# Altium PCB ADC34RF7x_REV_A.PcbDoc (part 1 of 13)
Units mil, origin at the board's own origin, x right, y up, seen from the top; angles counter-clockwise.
Board outline 6250 x 2716.54 mil, 18 copper layers (Top Layer, L2 GND, L3 PWR, L4 GND, L5 PWR/SIG, L6 GND, L7 SIGNAL, L8 GND, L9 GND, L10 SIGNAL, L11 GND, L12 SIGNAL, L13 GND, L14 PWR, L15 GND, L16 PWR/SIG, L16 GND, Bottom Layer), stack 95.314 mil thick; 668 components, 786 nets, 3150 pads, 2020 vias.
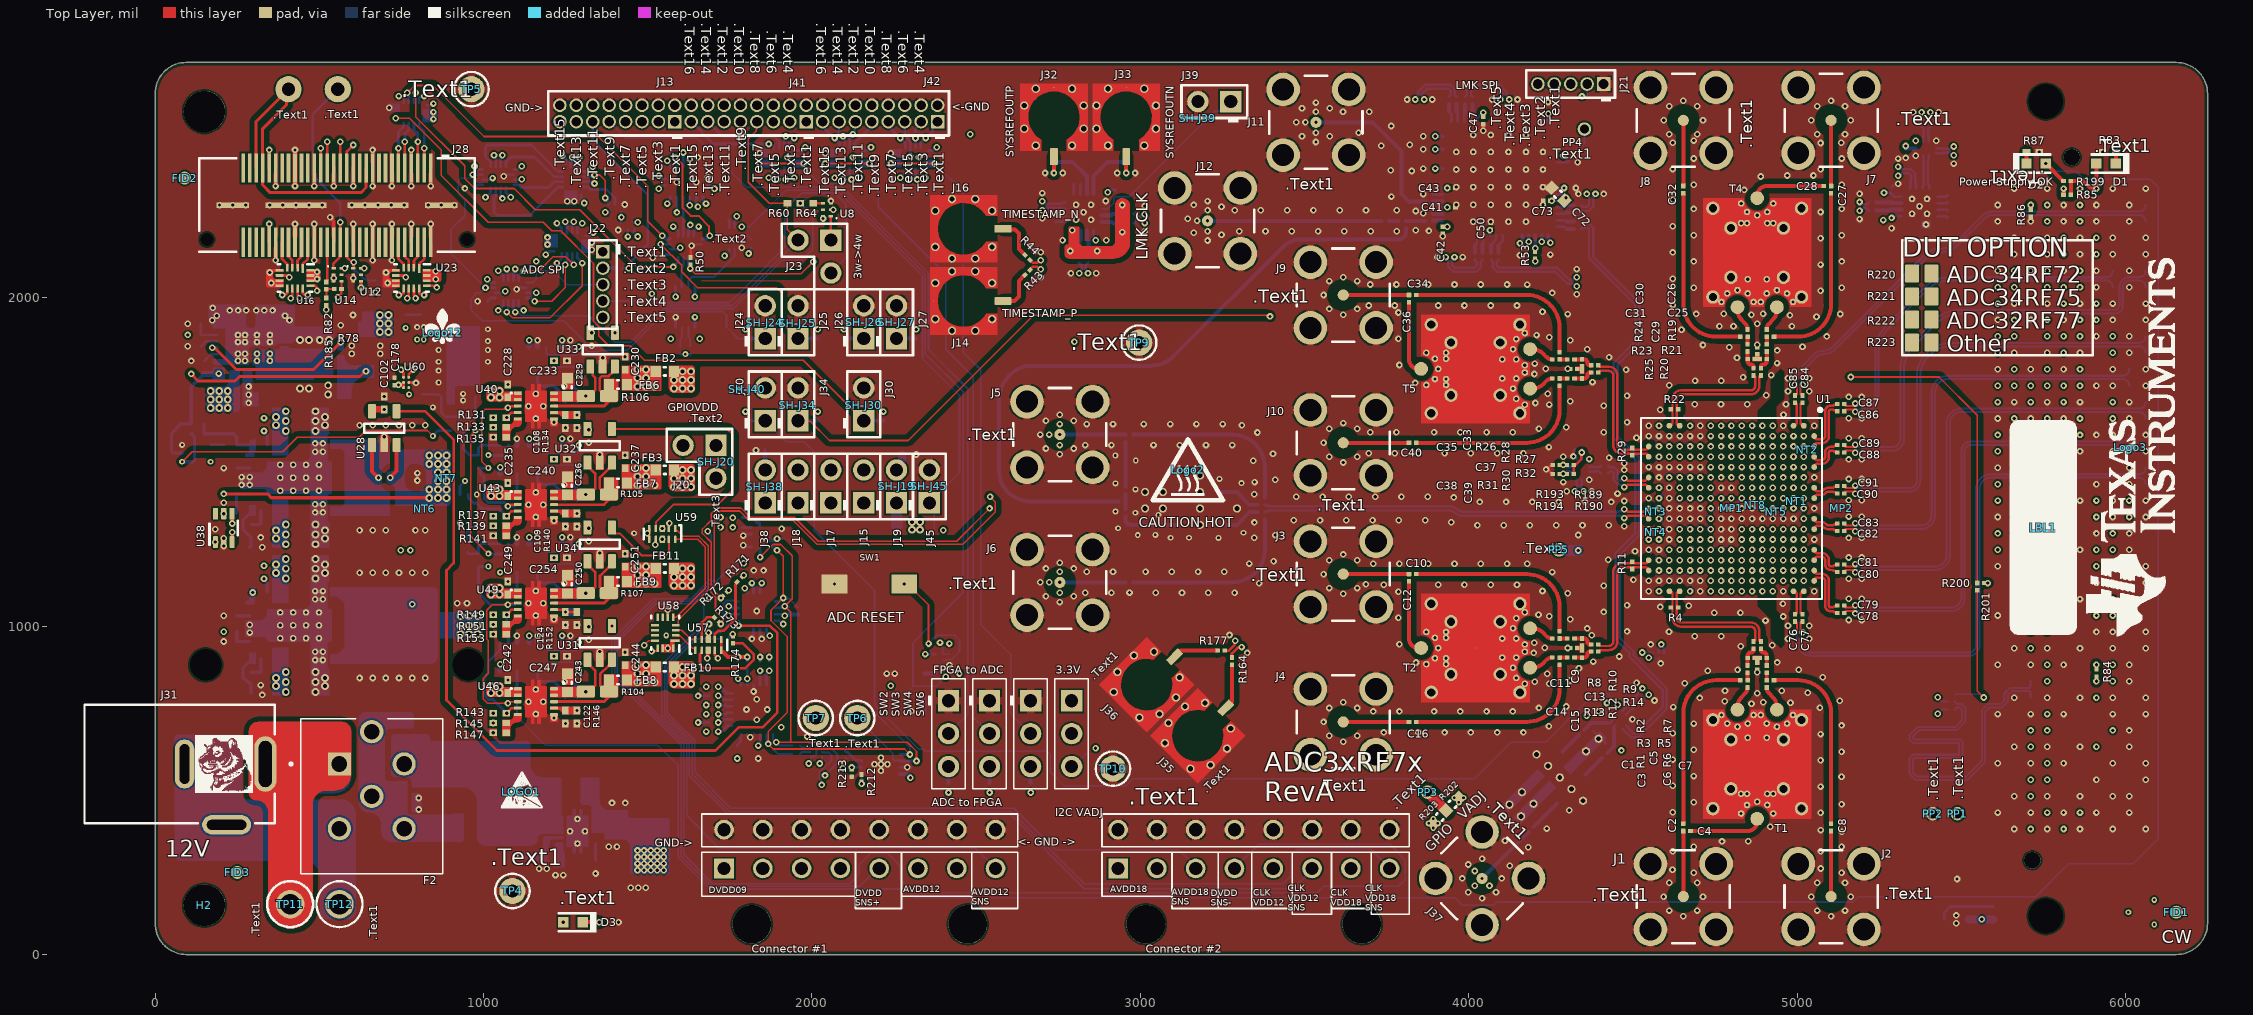
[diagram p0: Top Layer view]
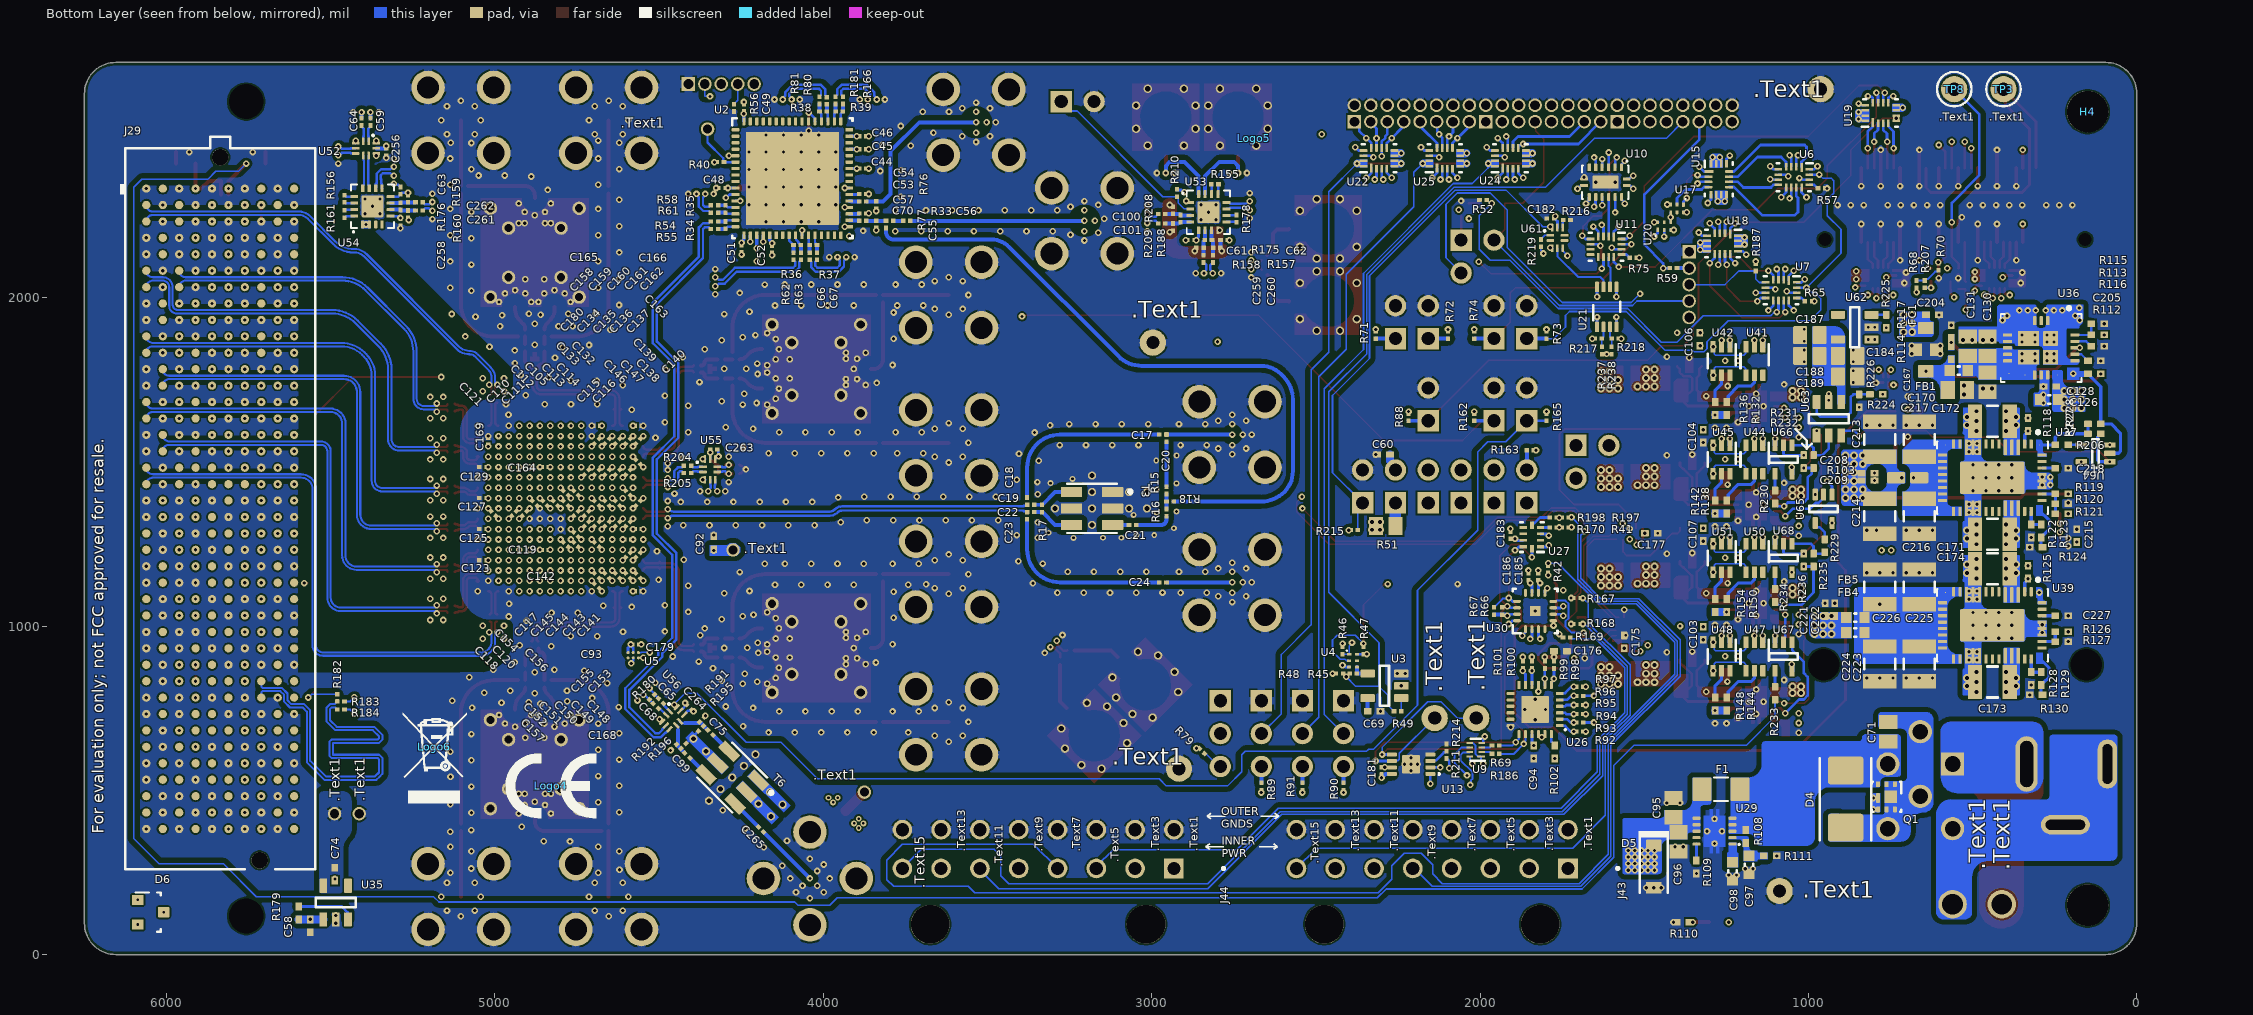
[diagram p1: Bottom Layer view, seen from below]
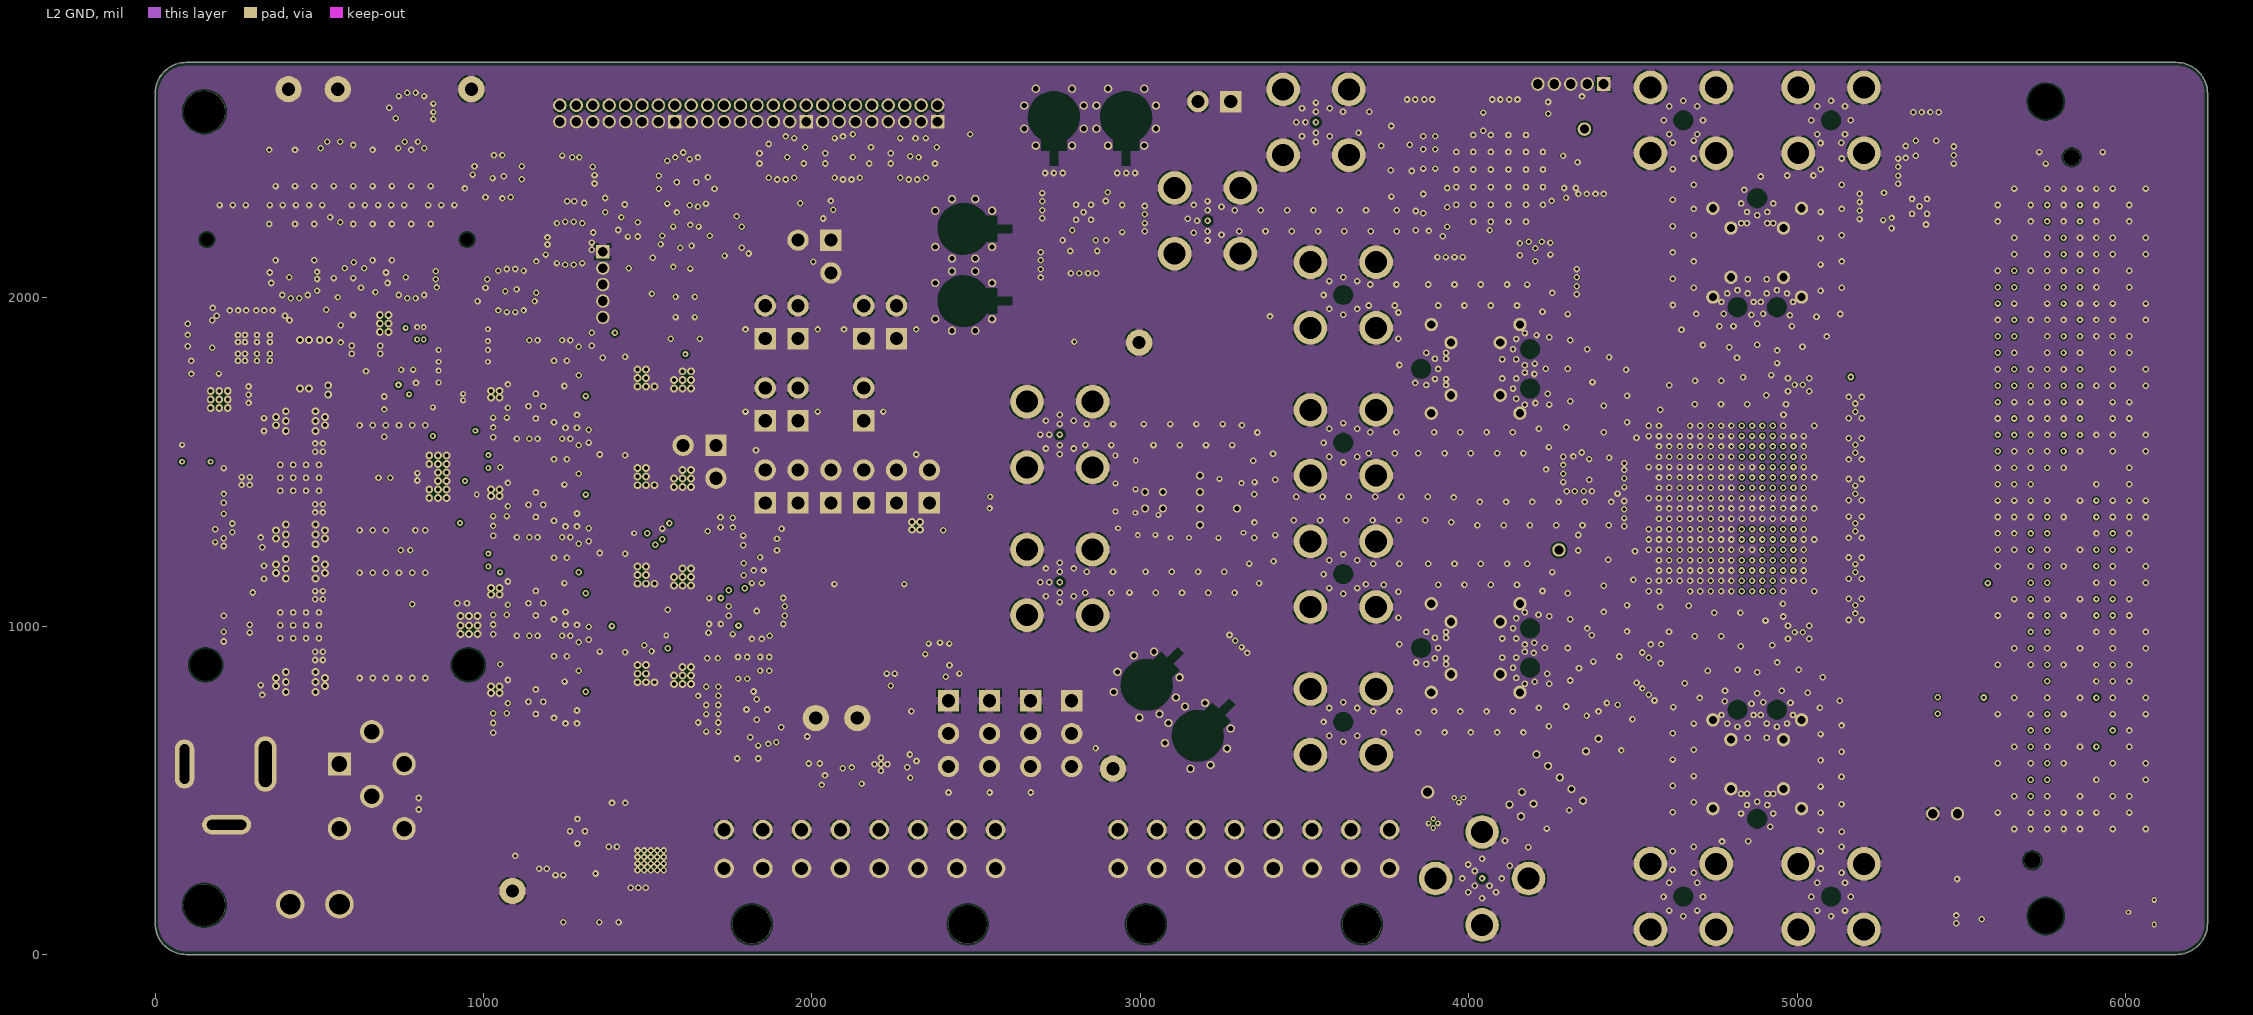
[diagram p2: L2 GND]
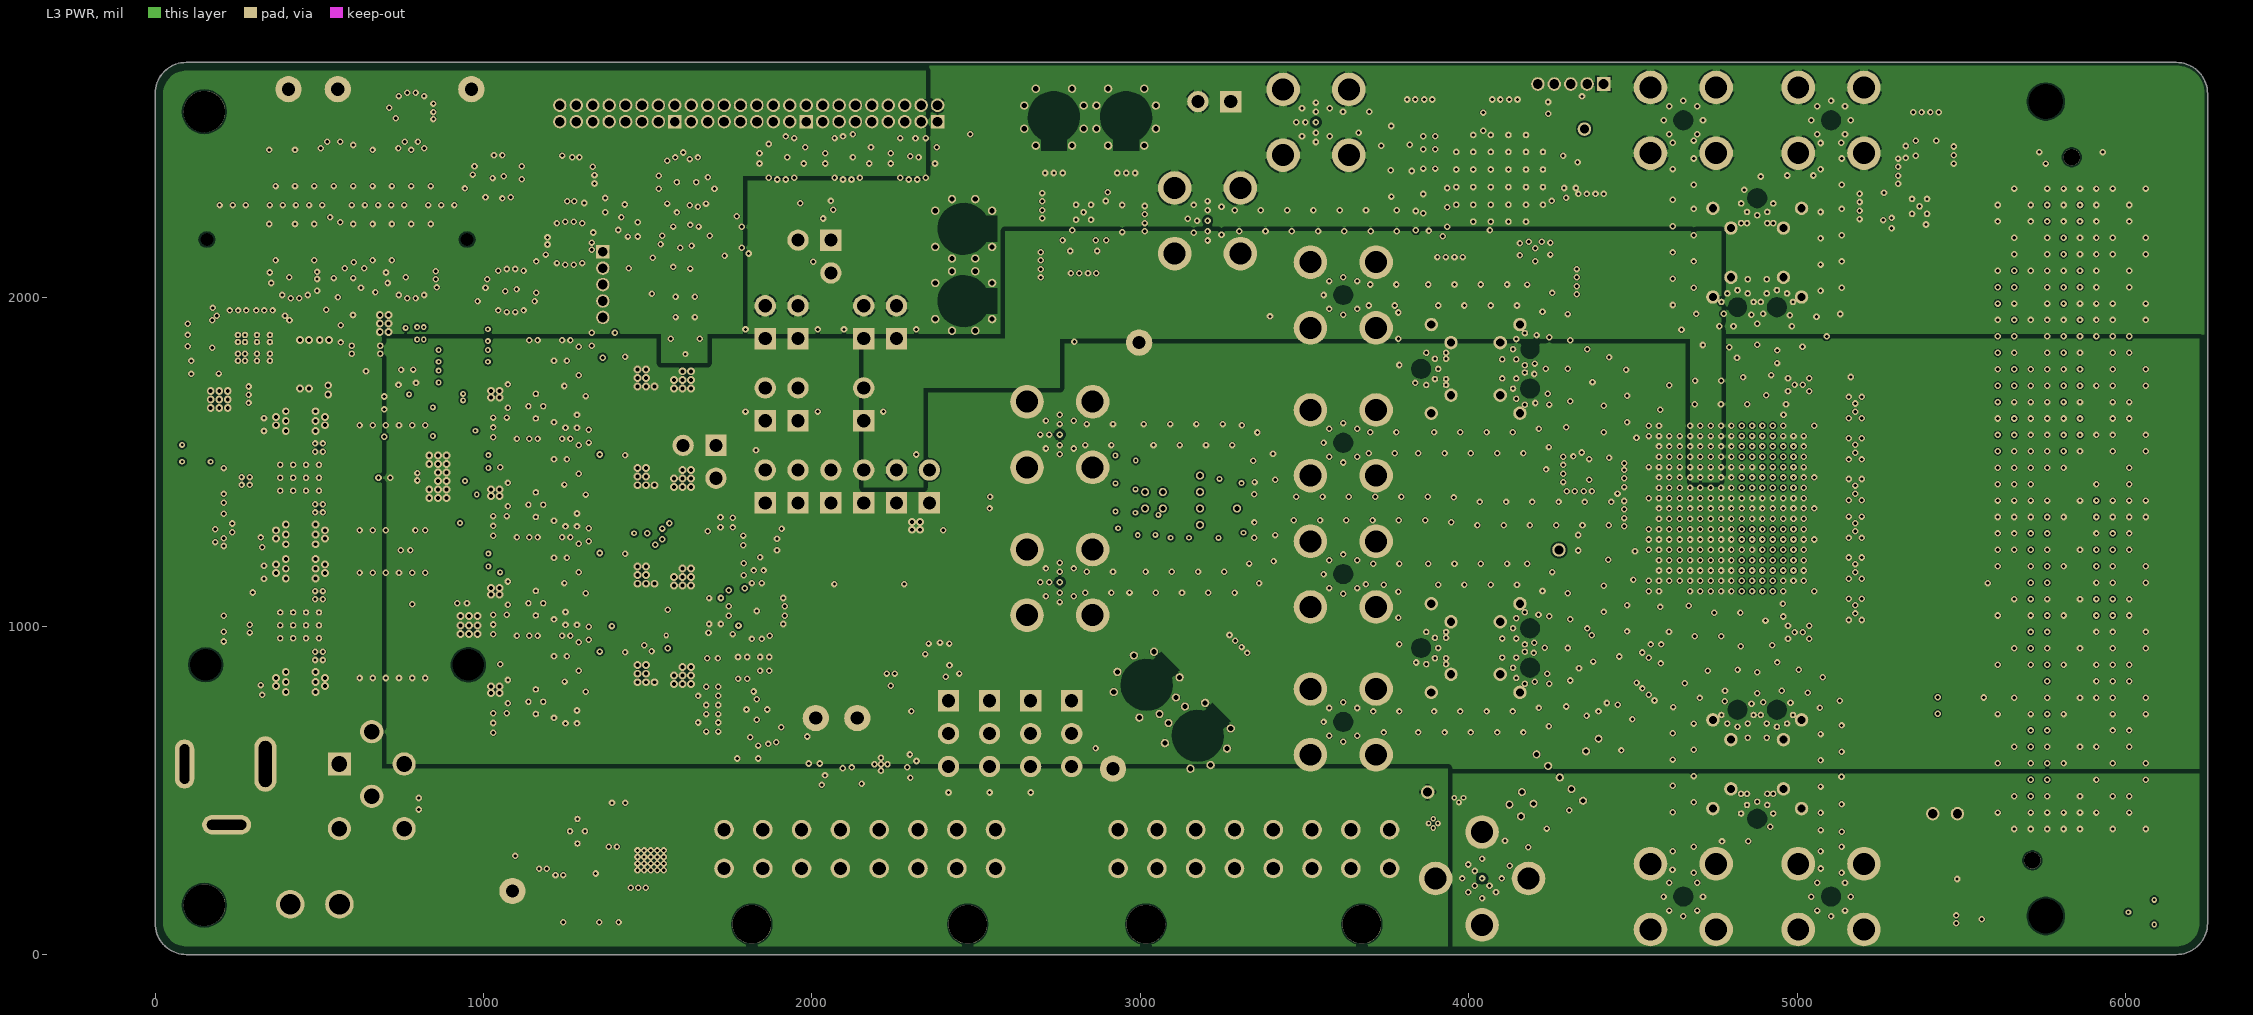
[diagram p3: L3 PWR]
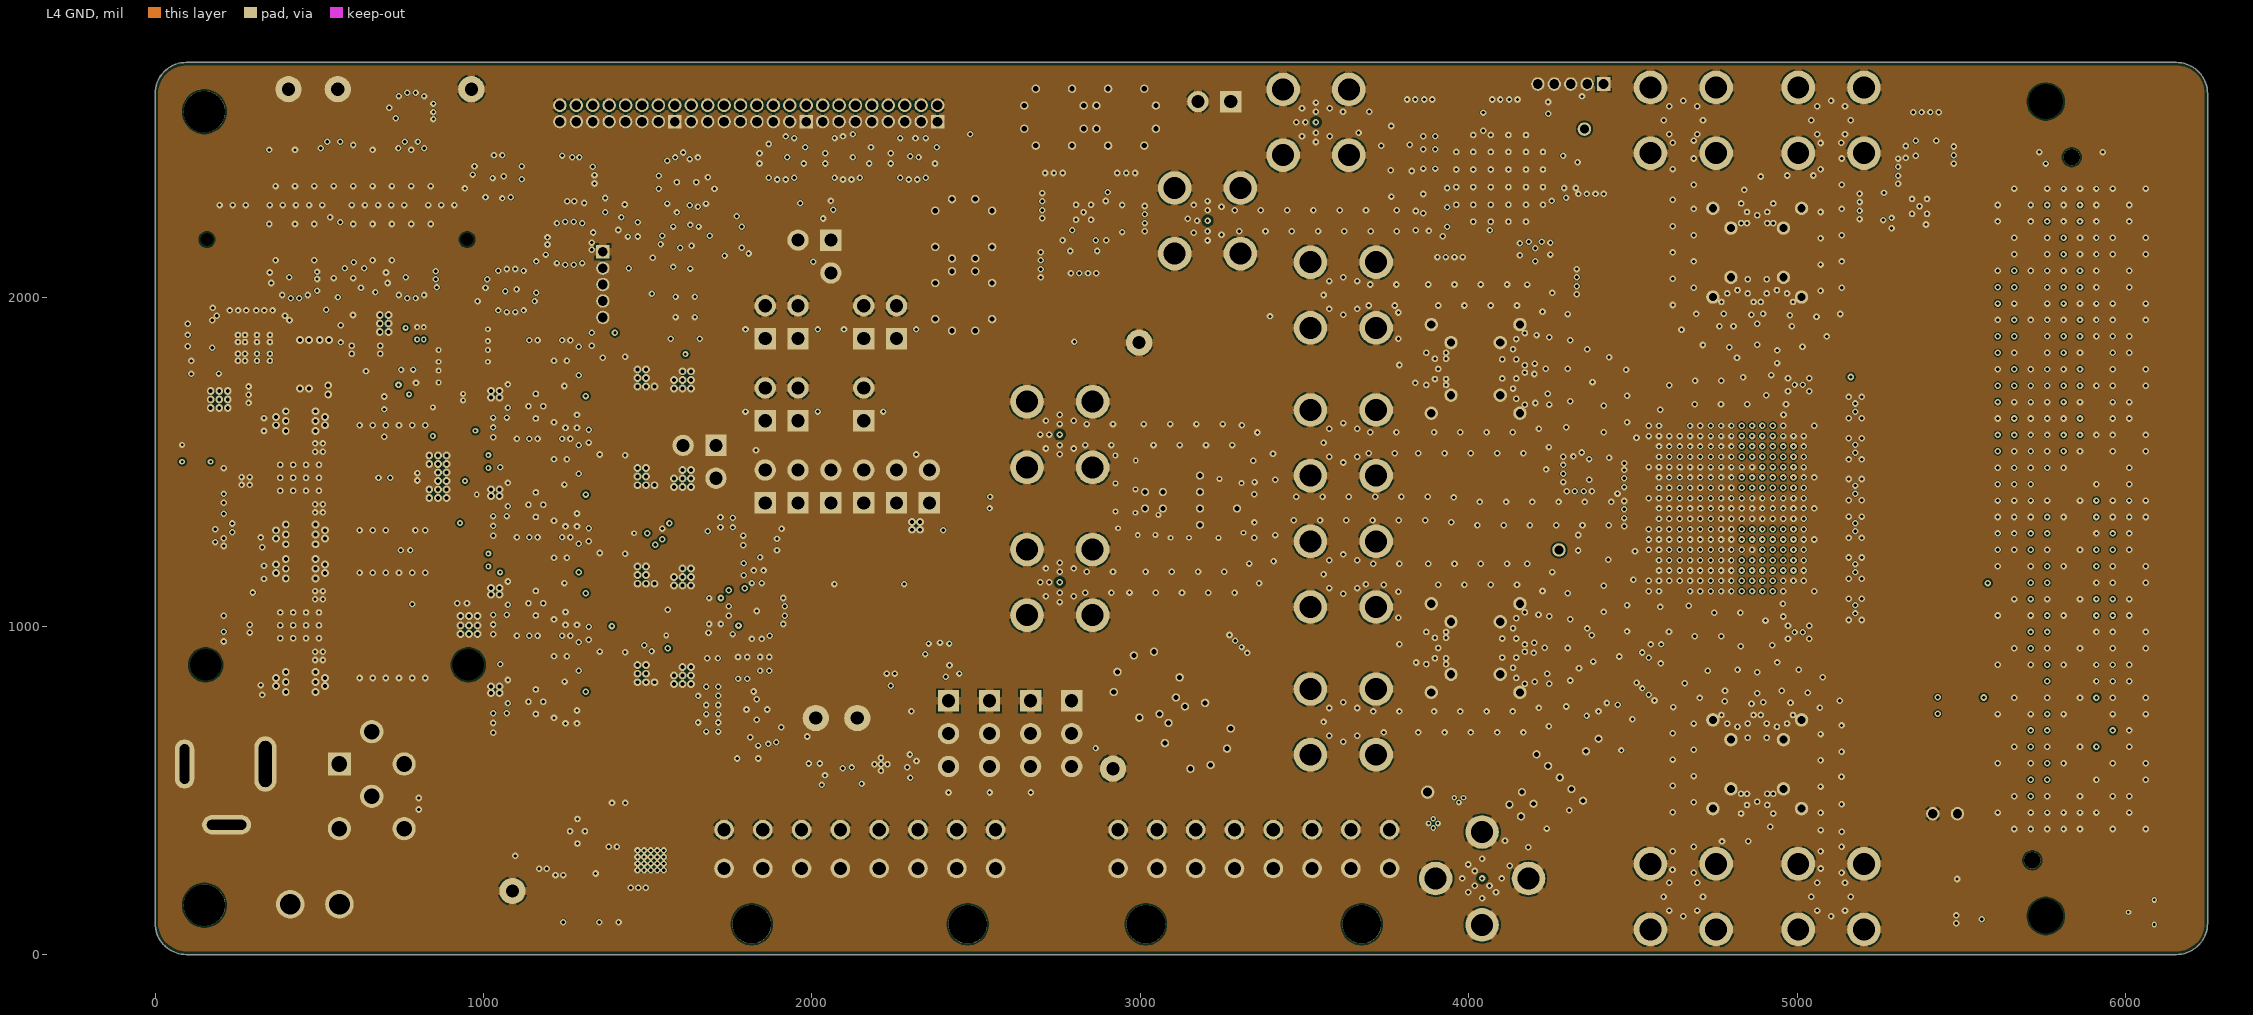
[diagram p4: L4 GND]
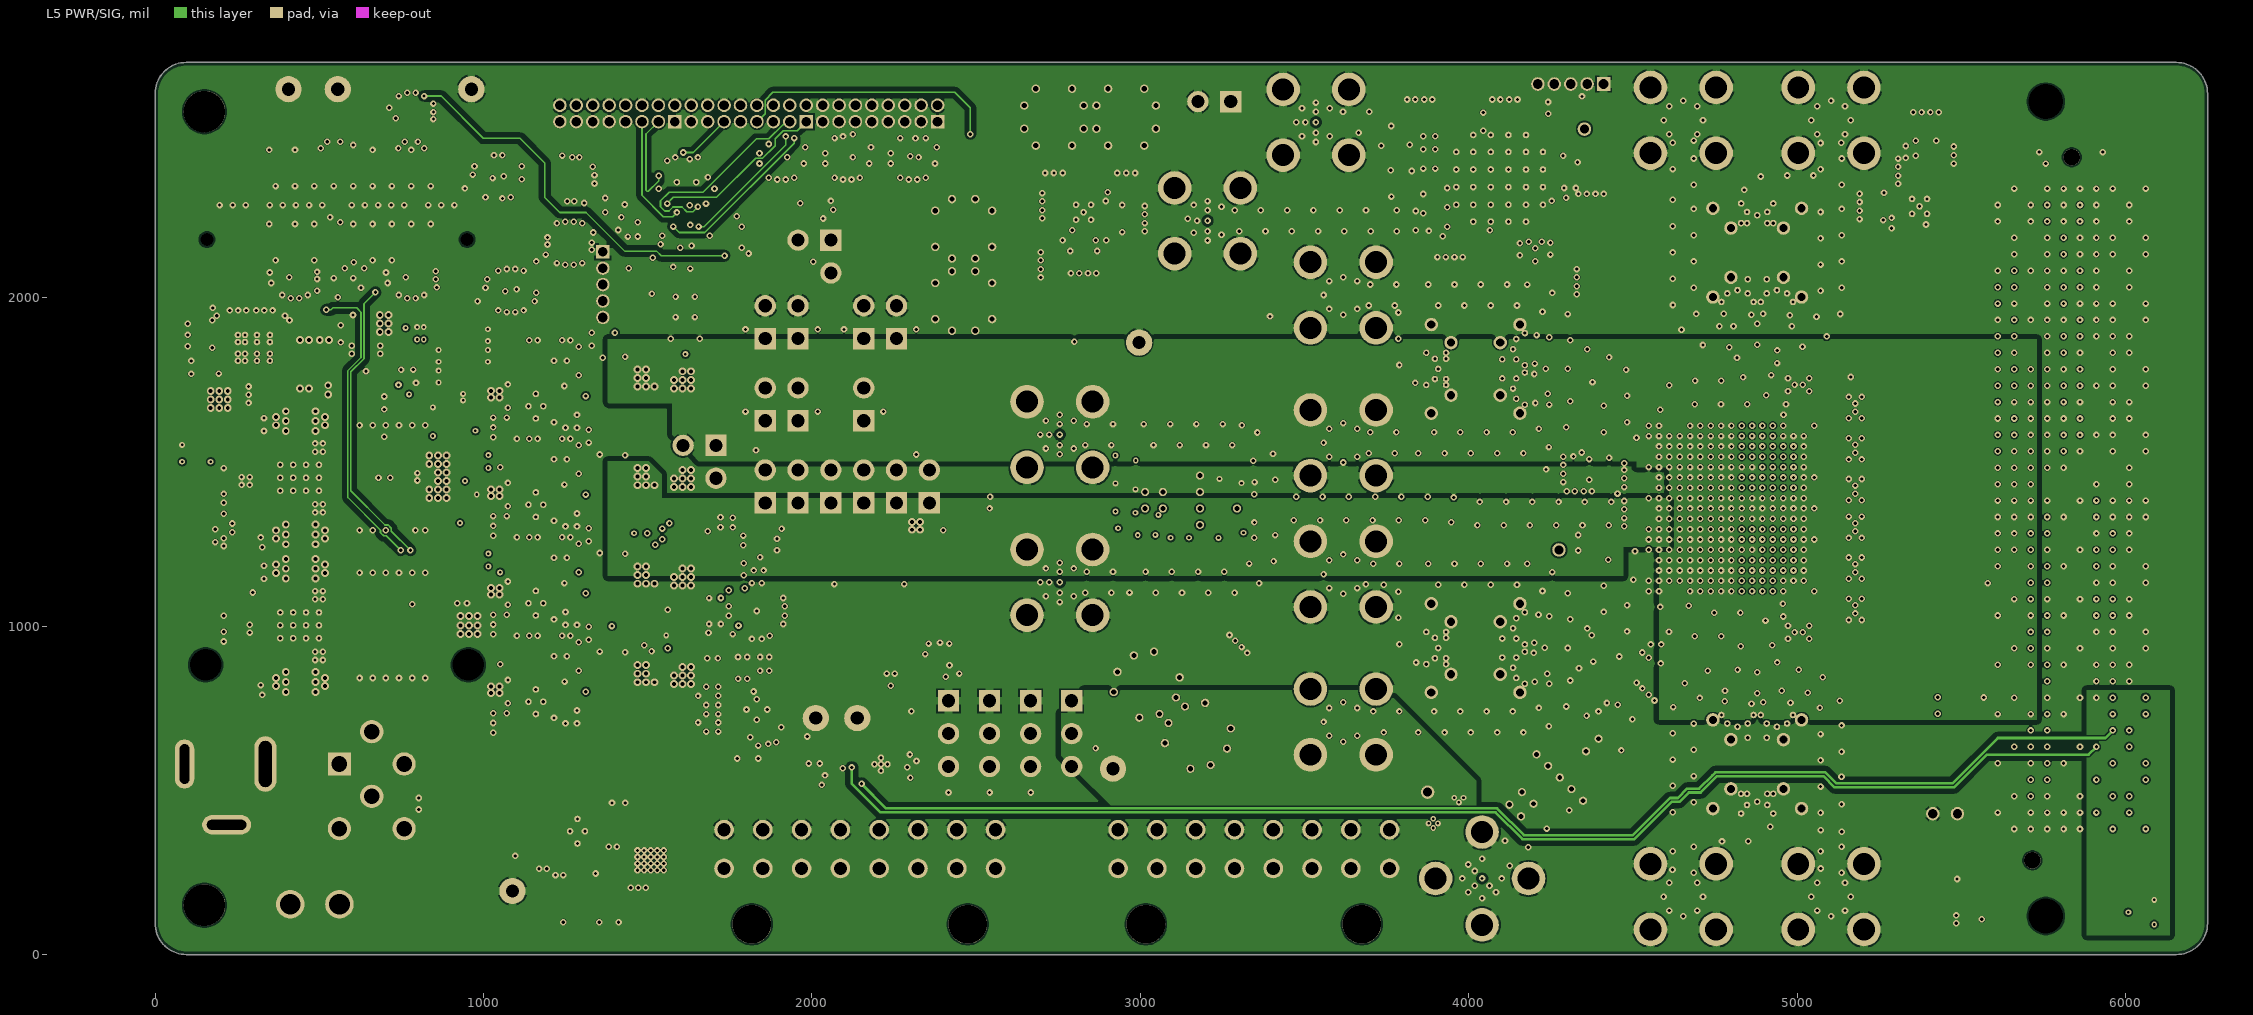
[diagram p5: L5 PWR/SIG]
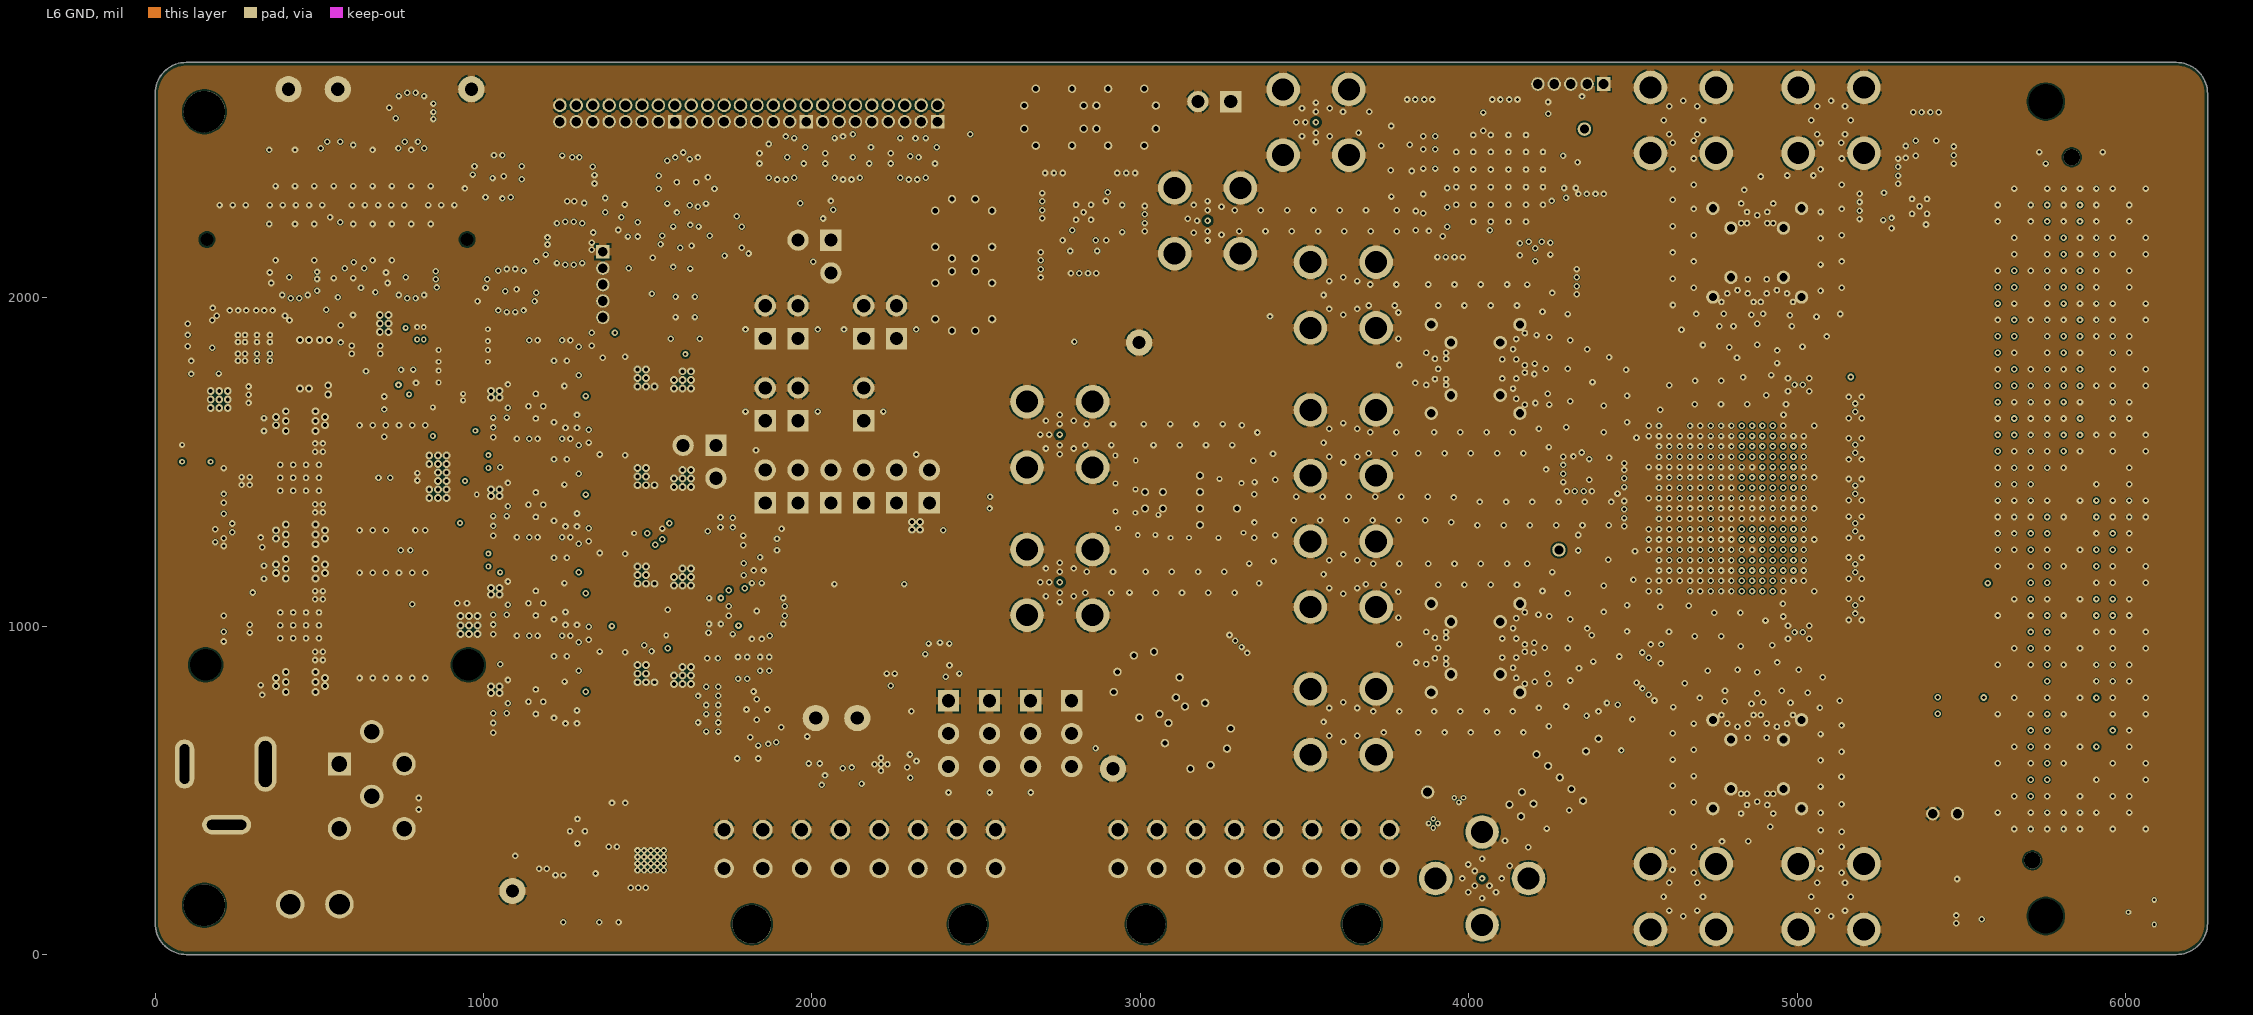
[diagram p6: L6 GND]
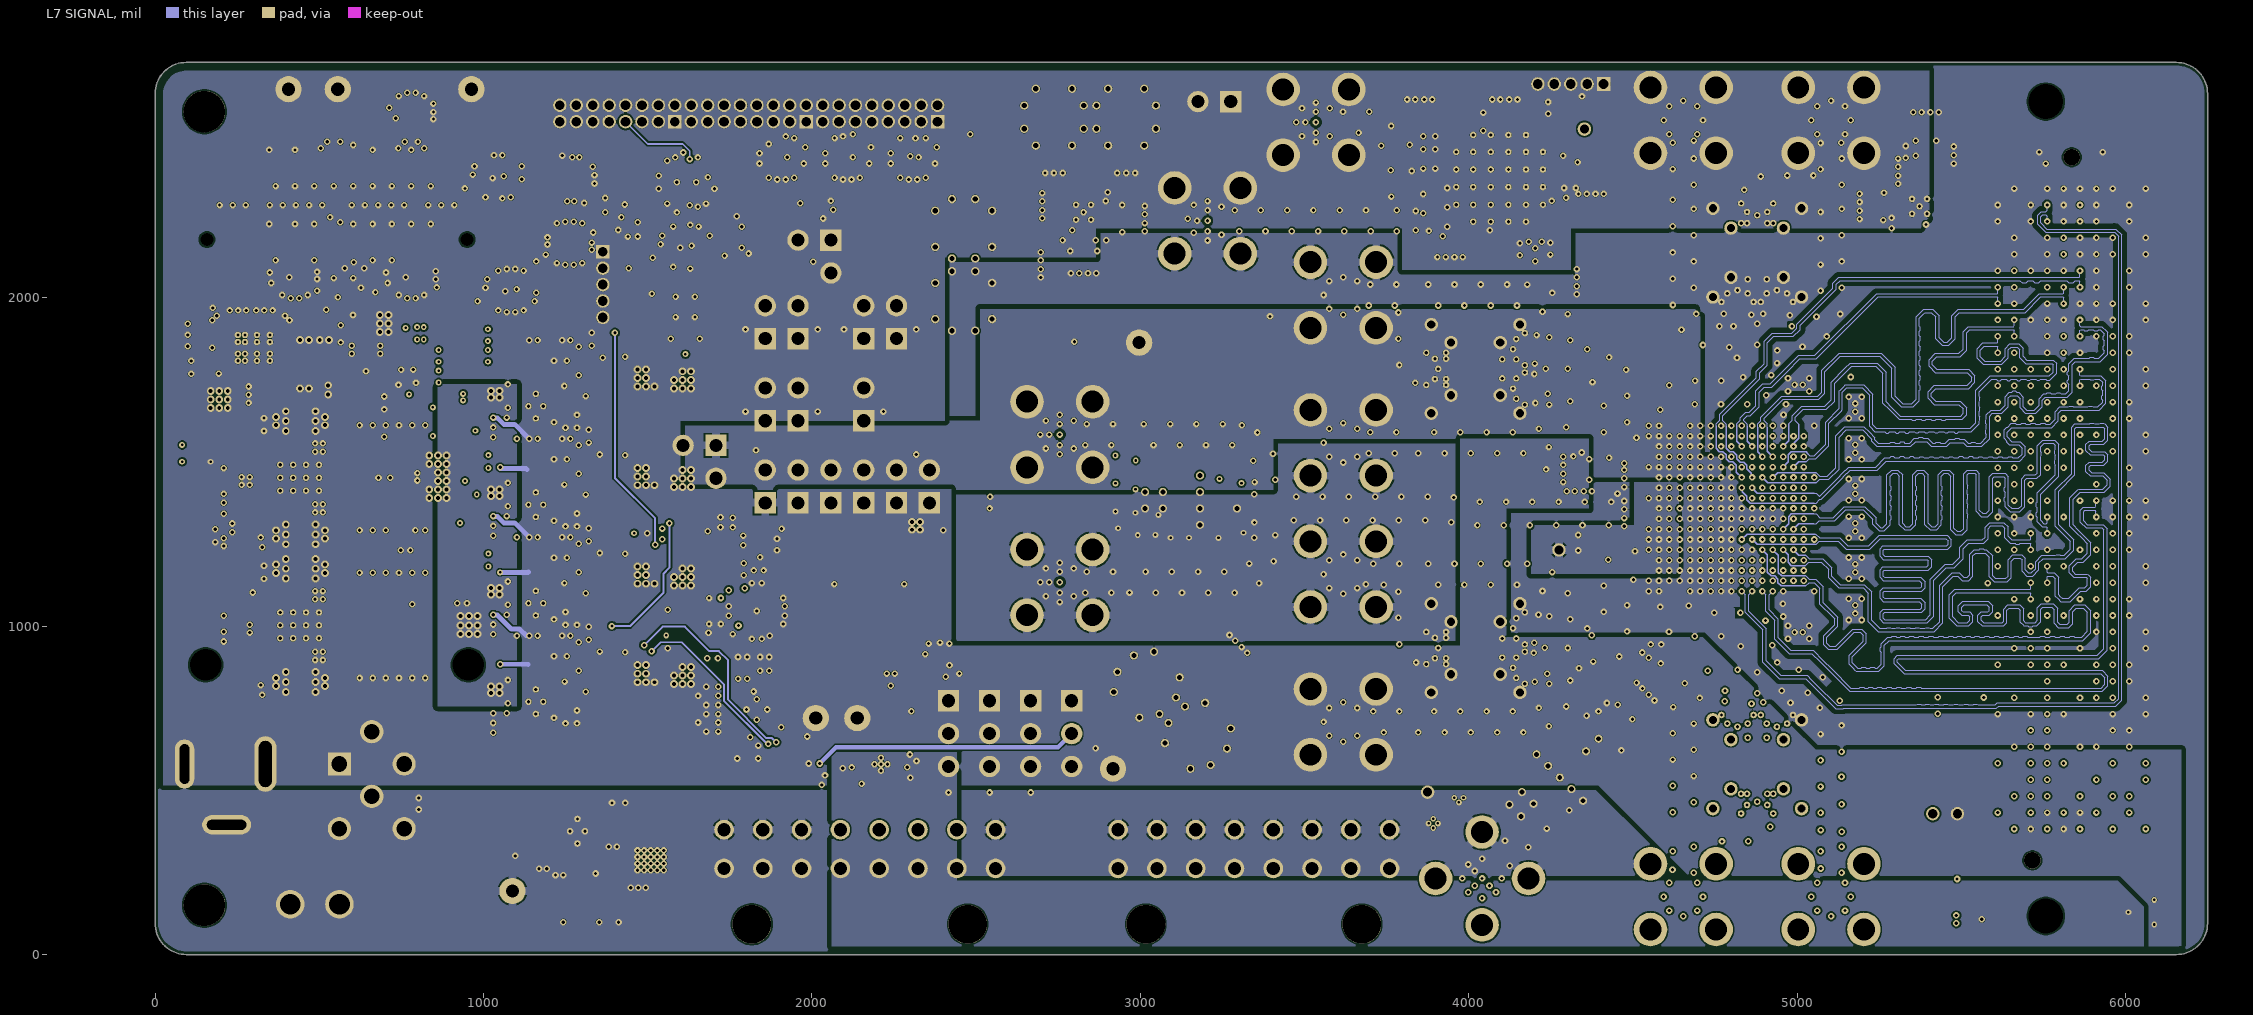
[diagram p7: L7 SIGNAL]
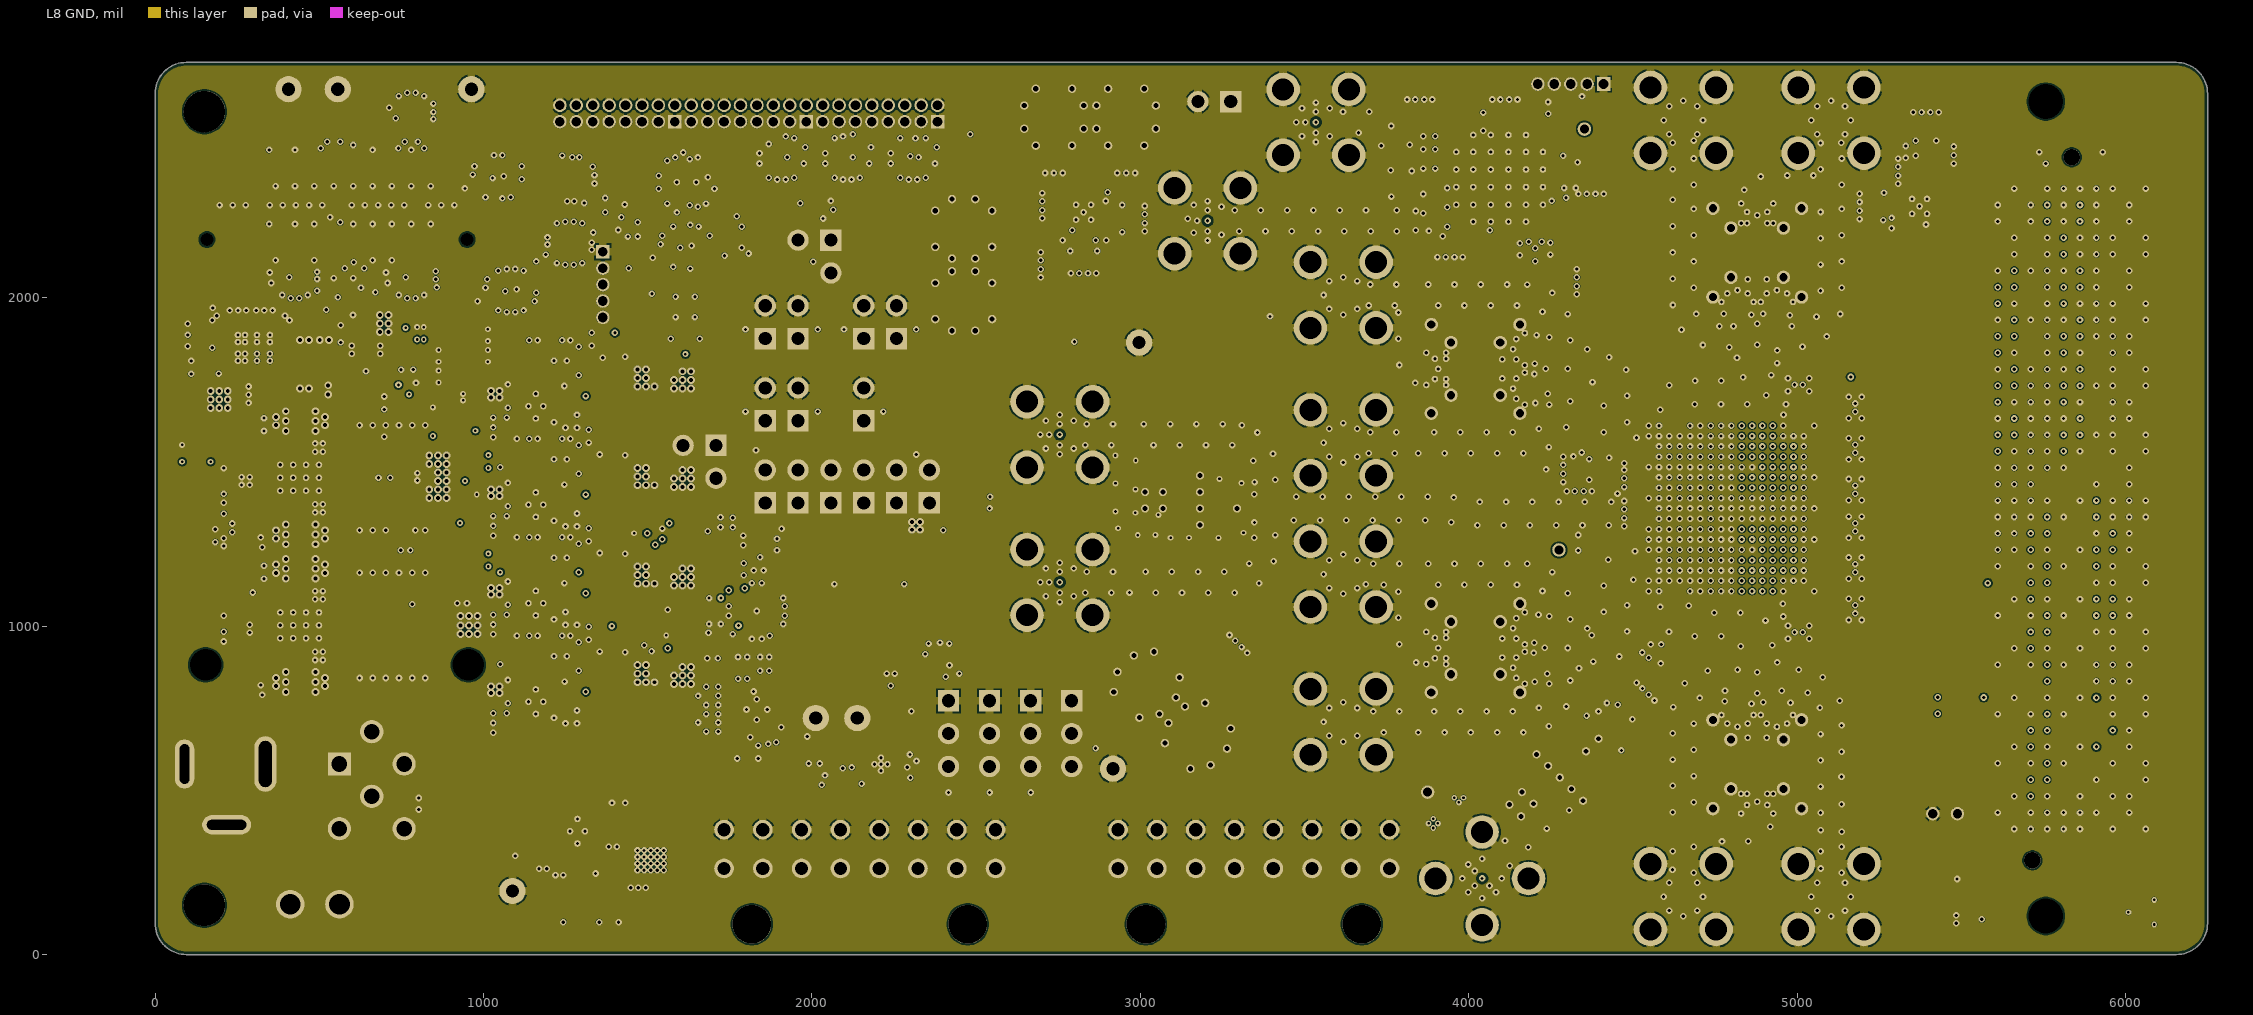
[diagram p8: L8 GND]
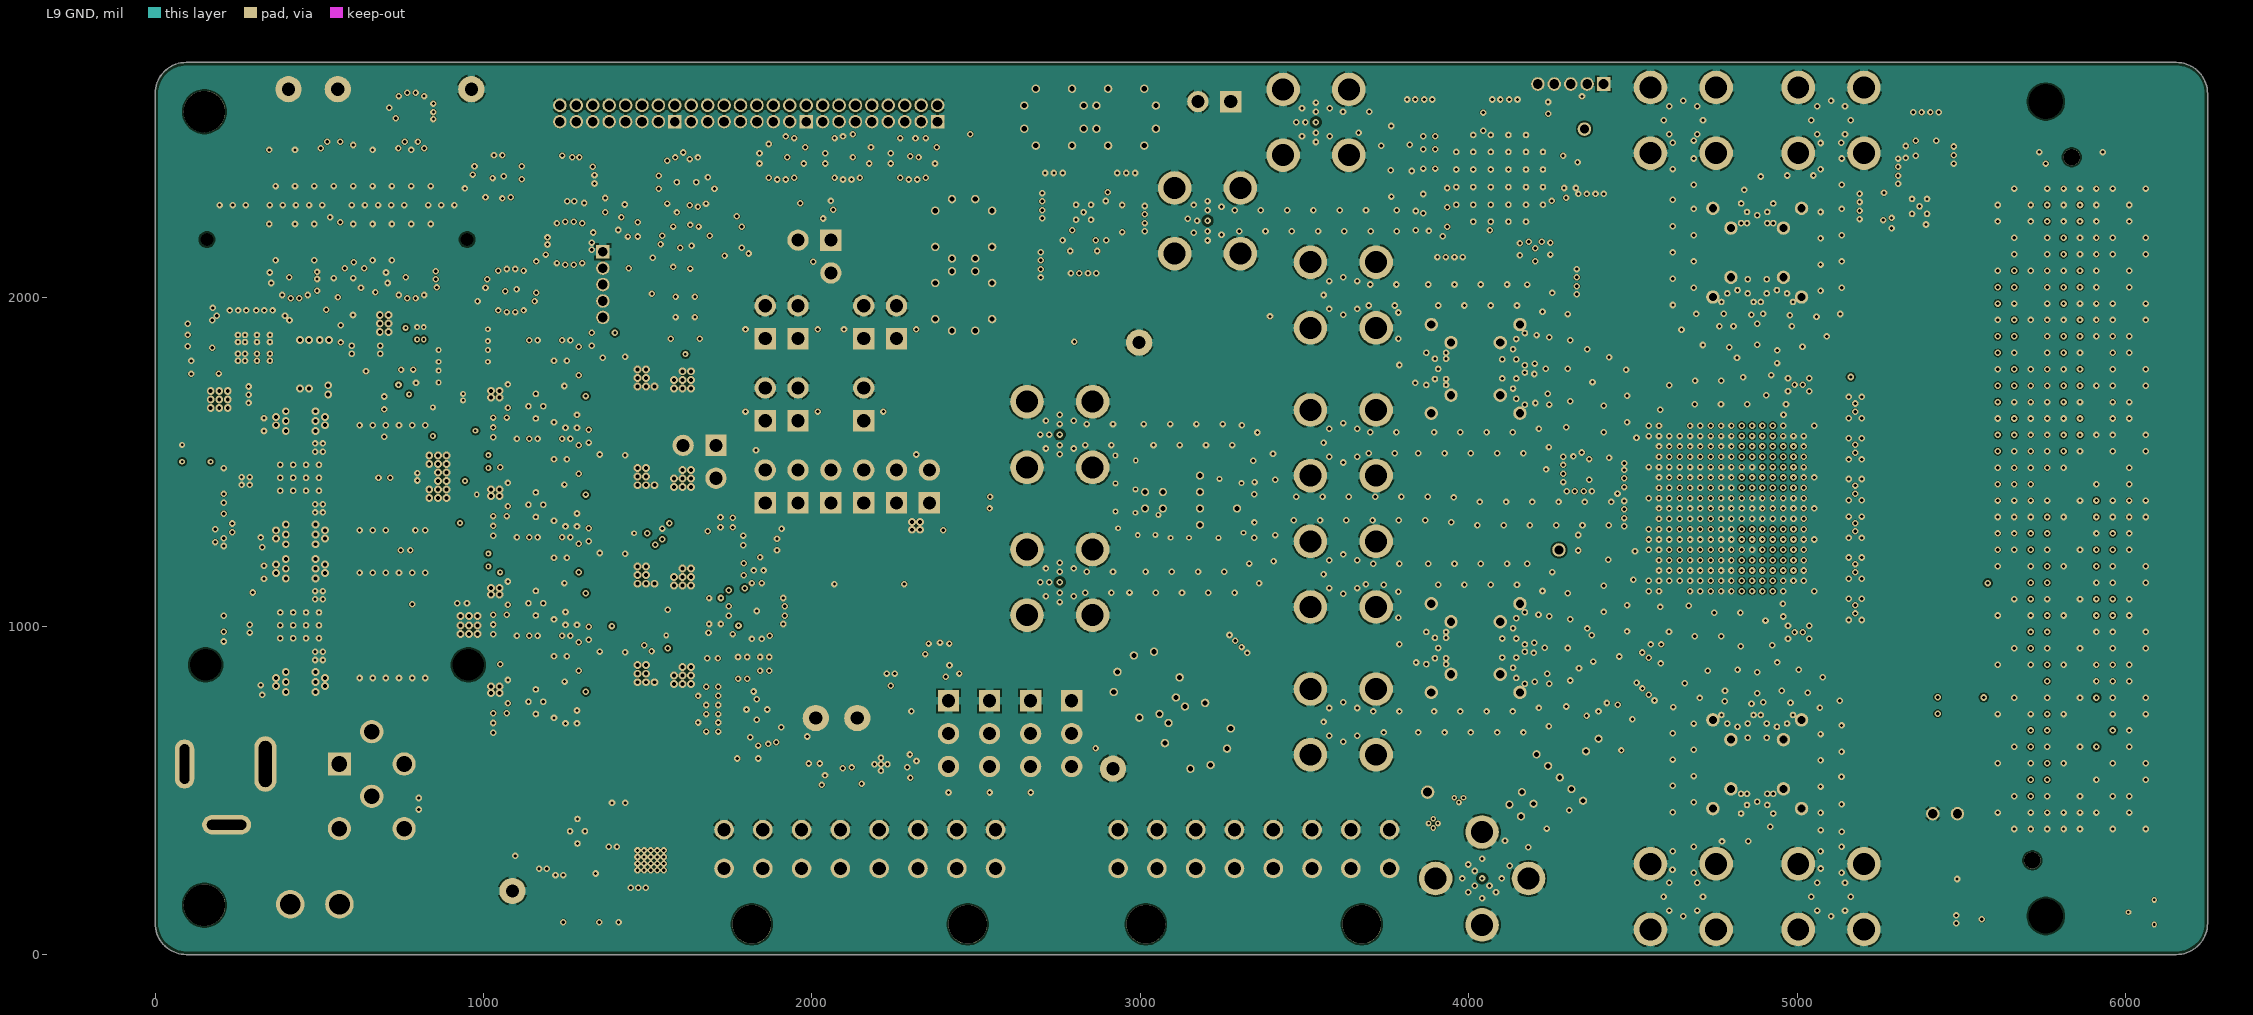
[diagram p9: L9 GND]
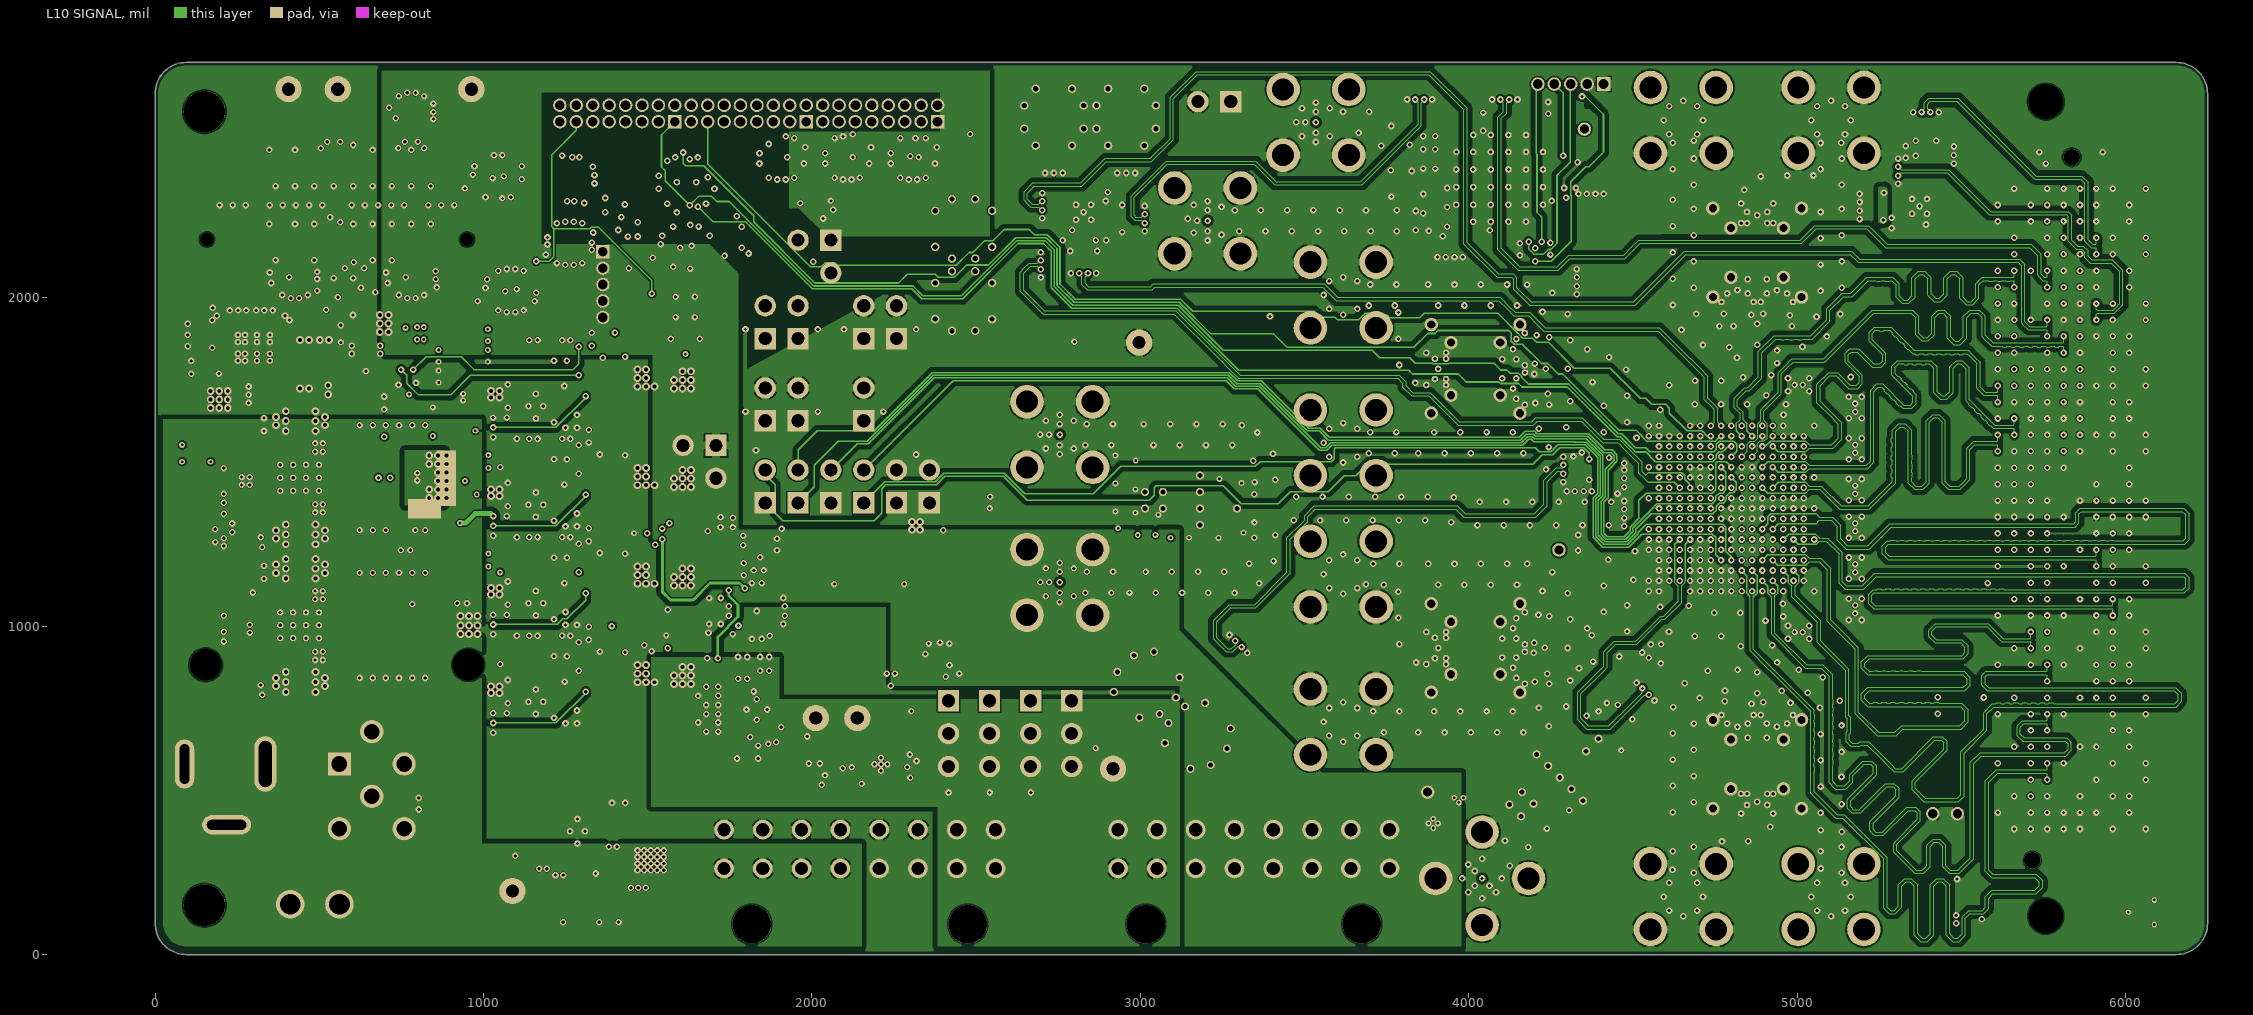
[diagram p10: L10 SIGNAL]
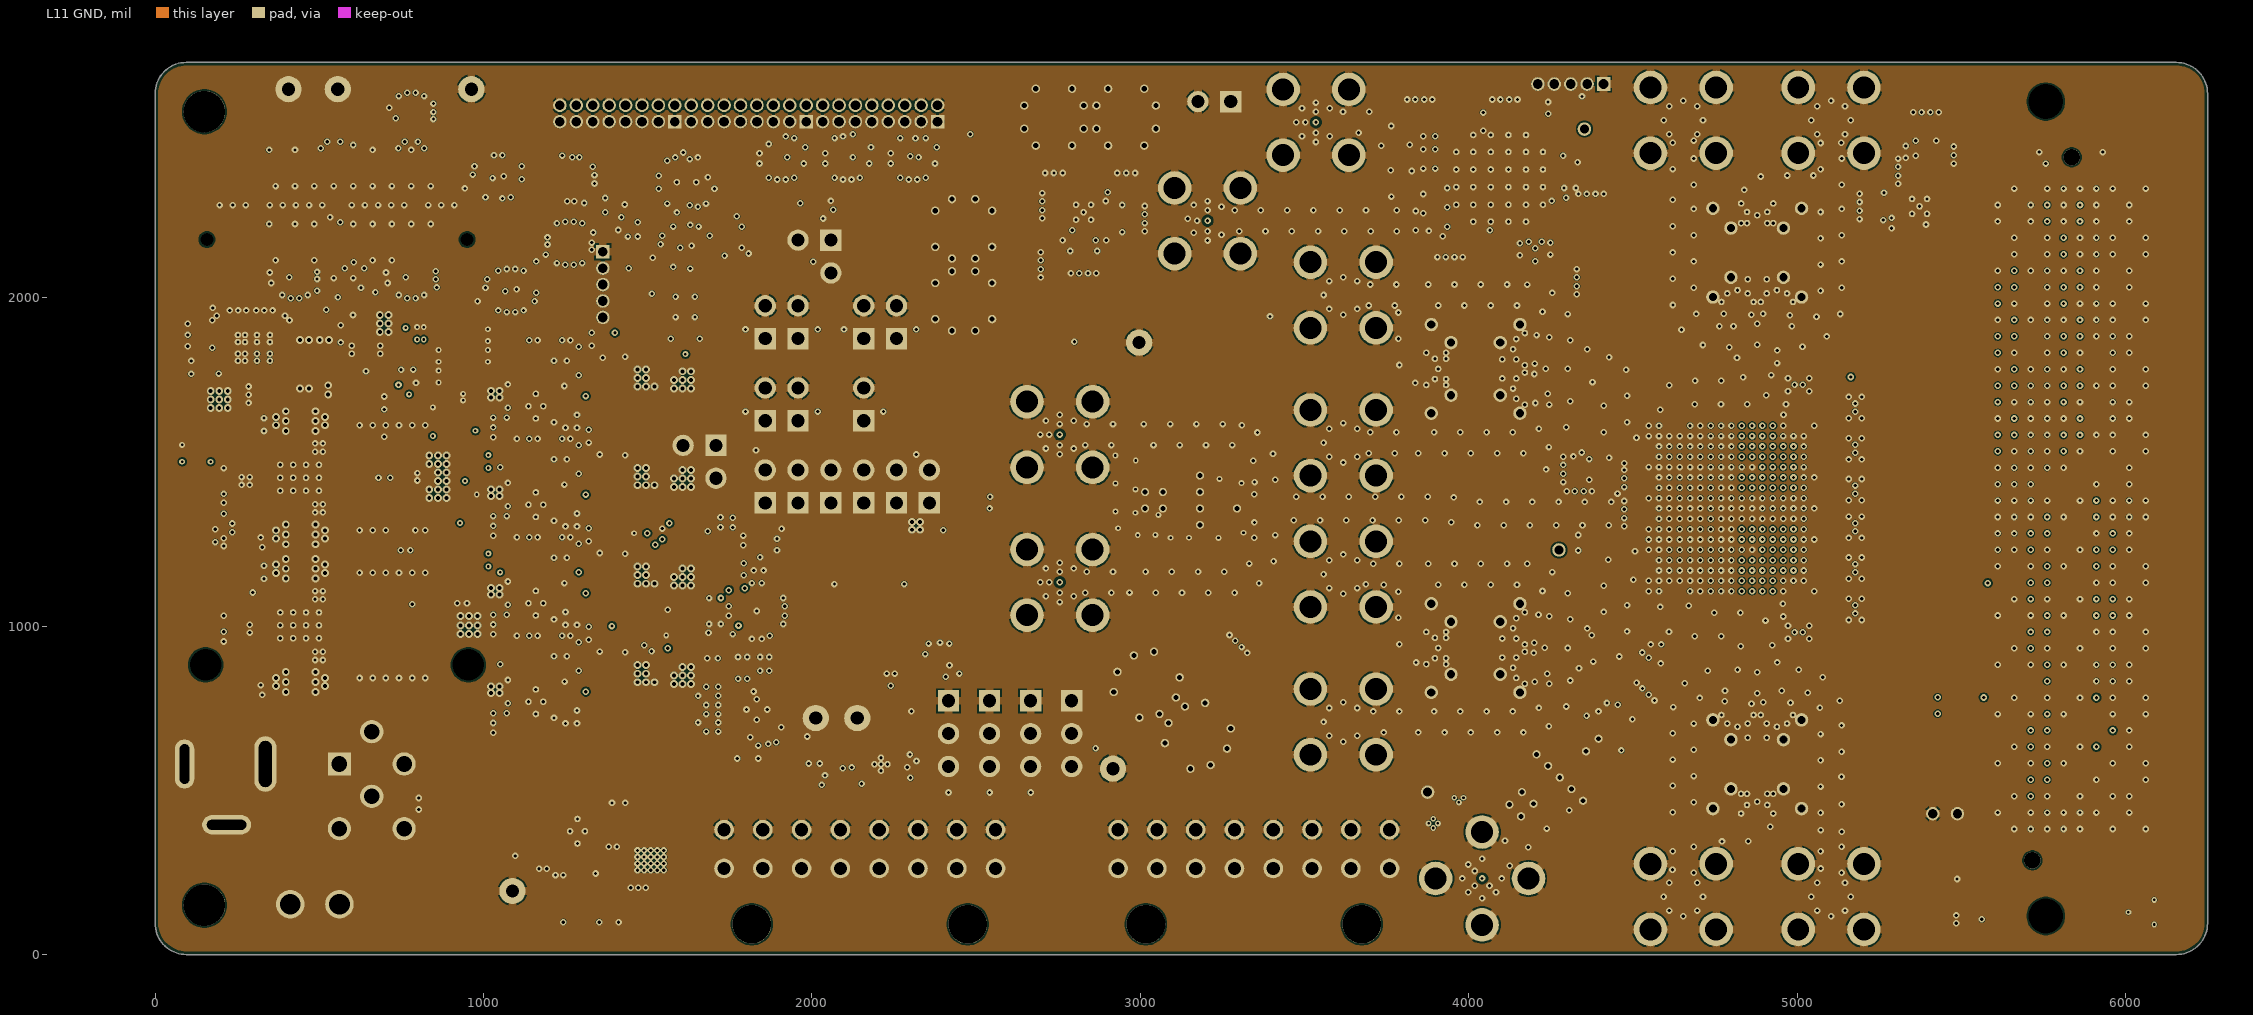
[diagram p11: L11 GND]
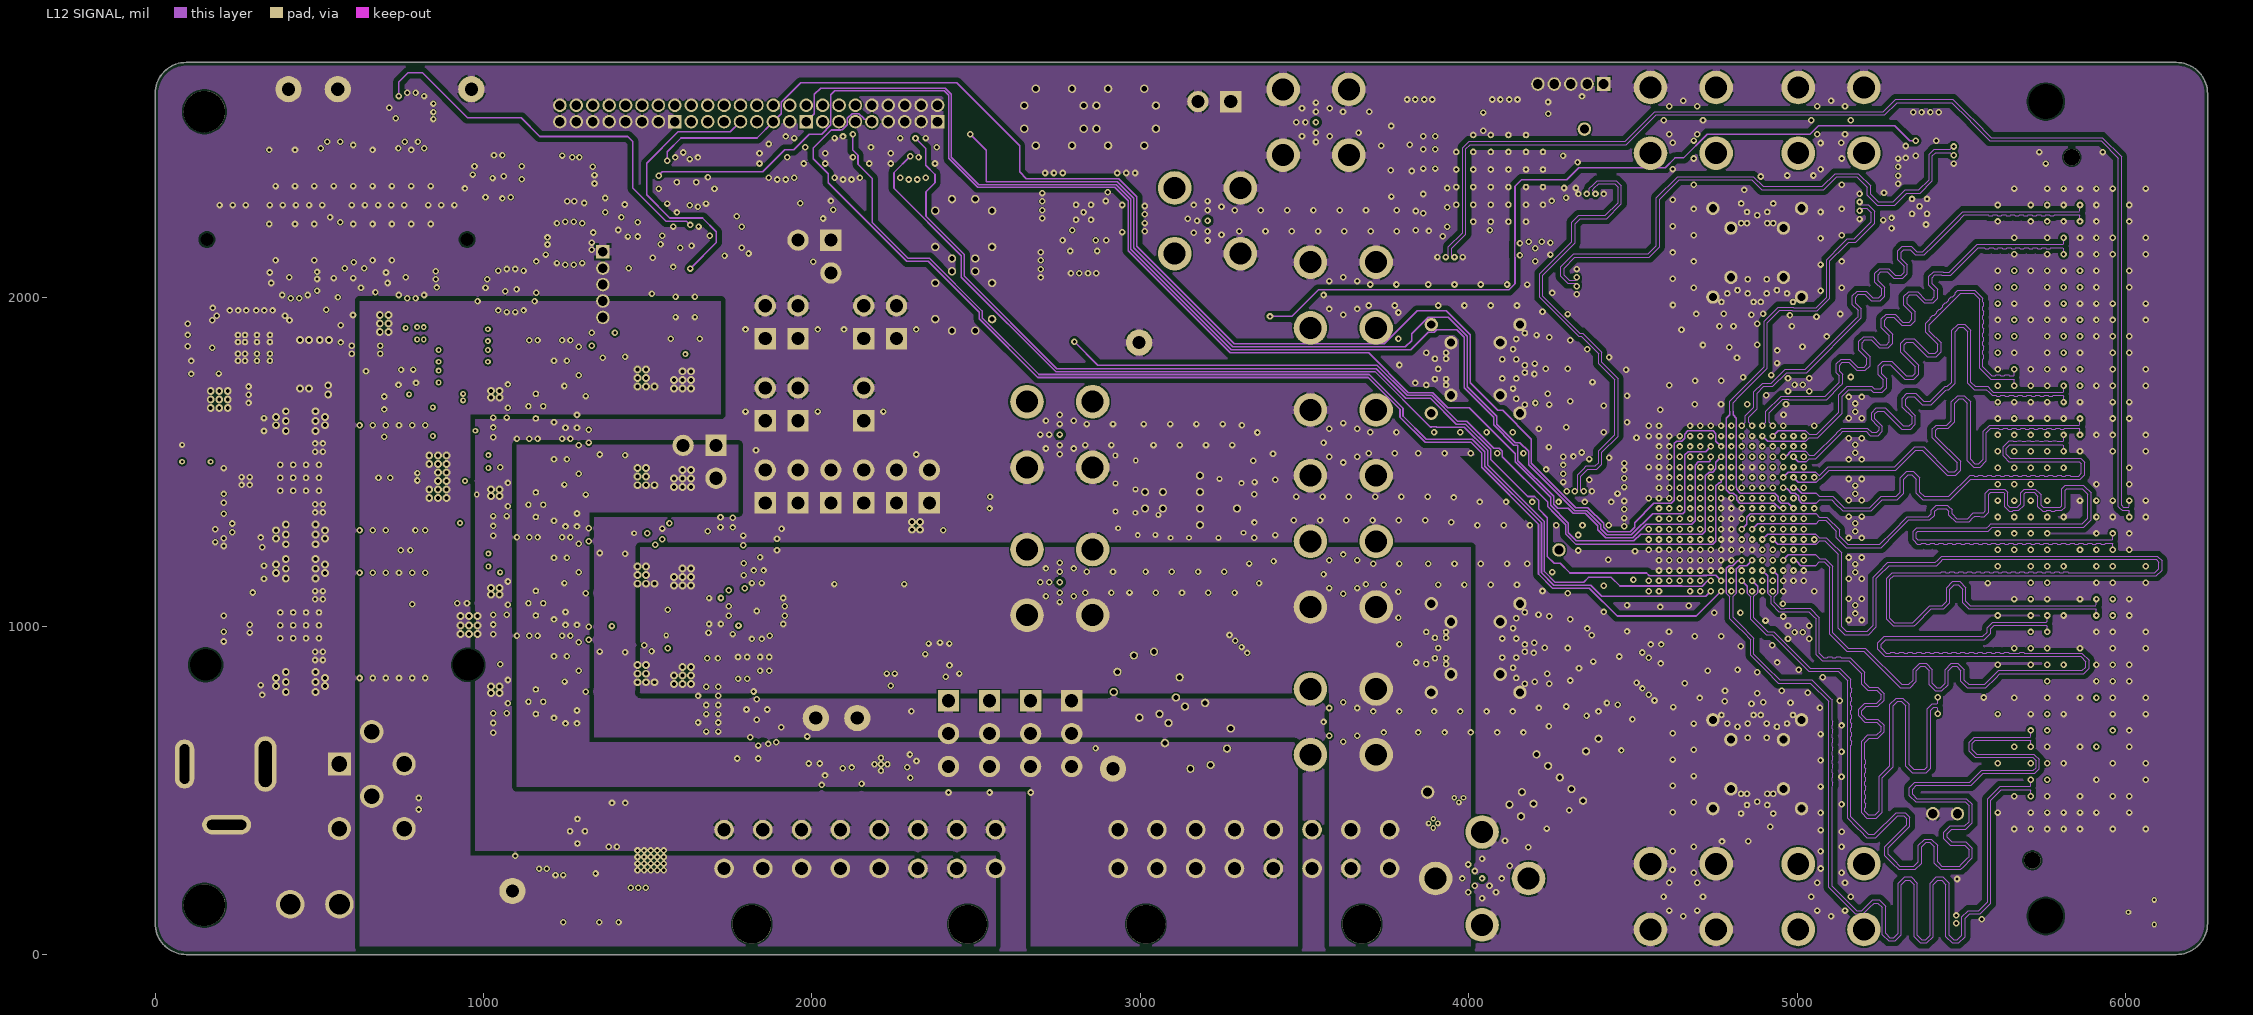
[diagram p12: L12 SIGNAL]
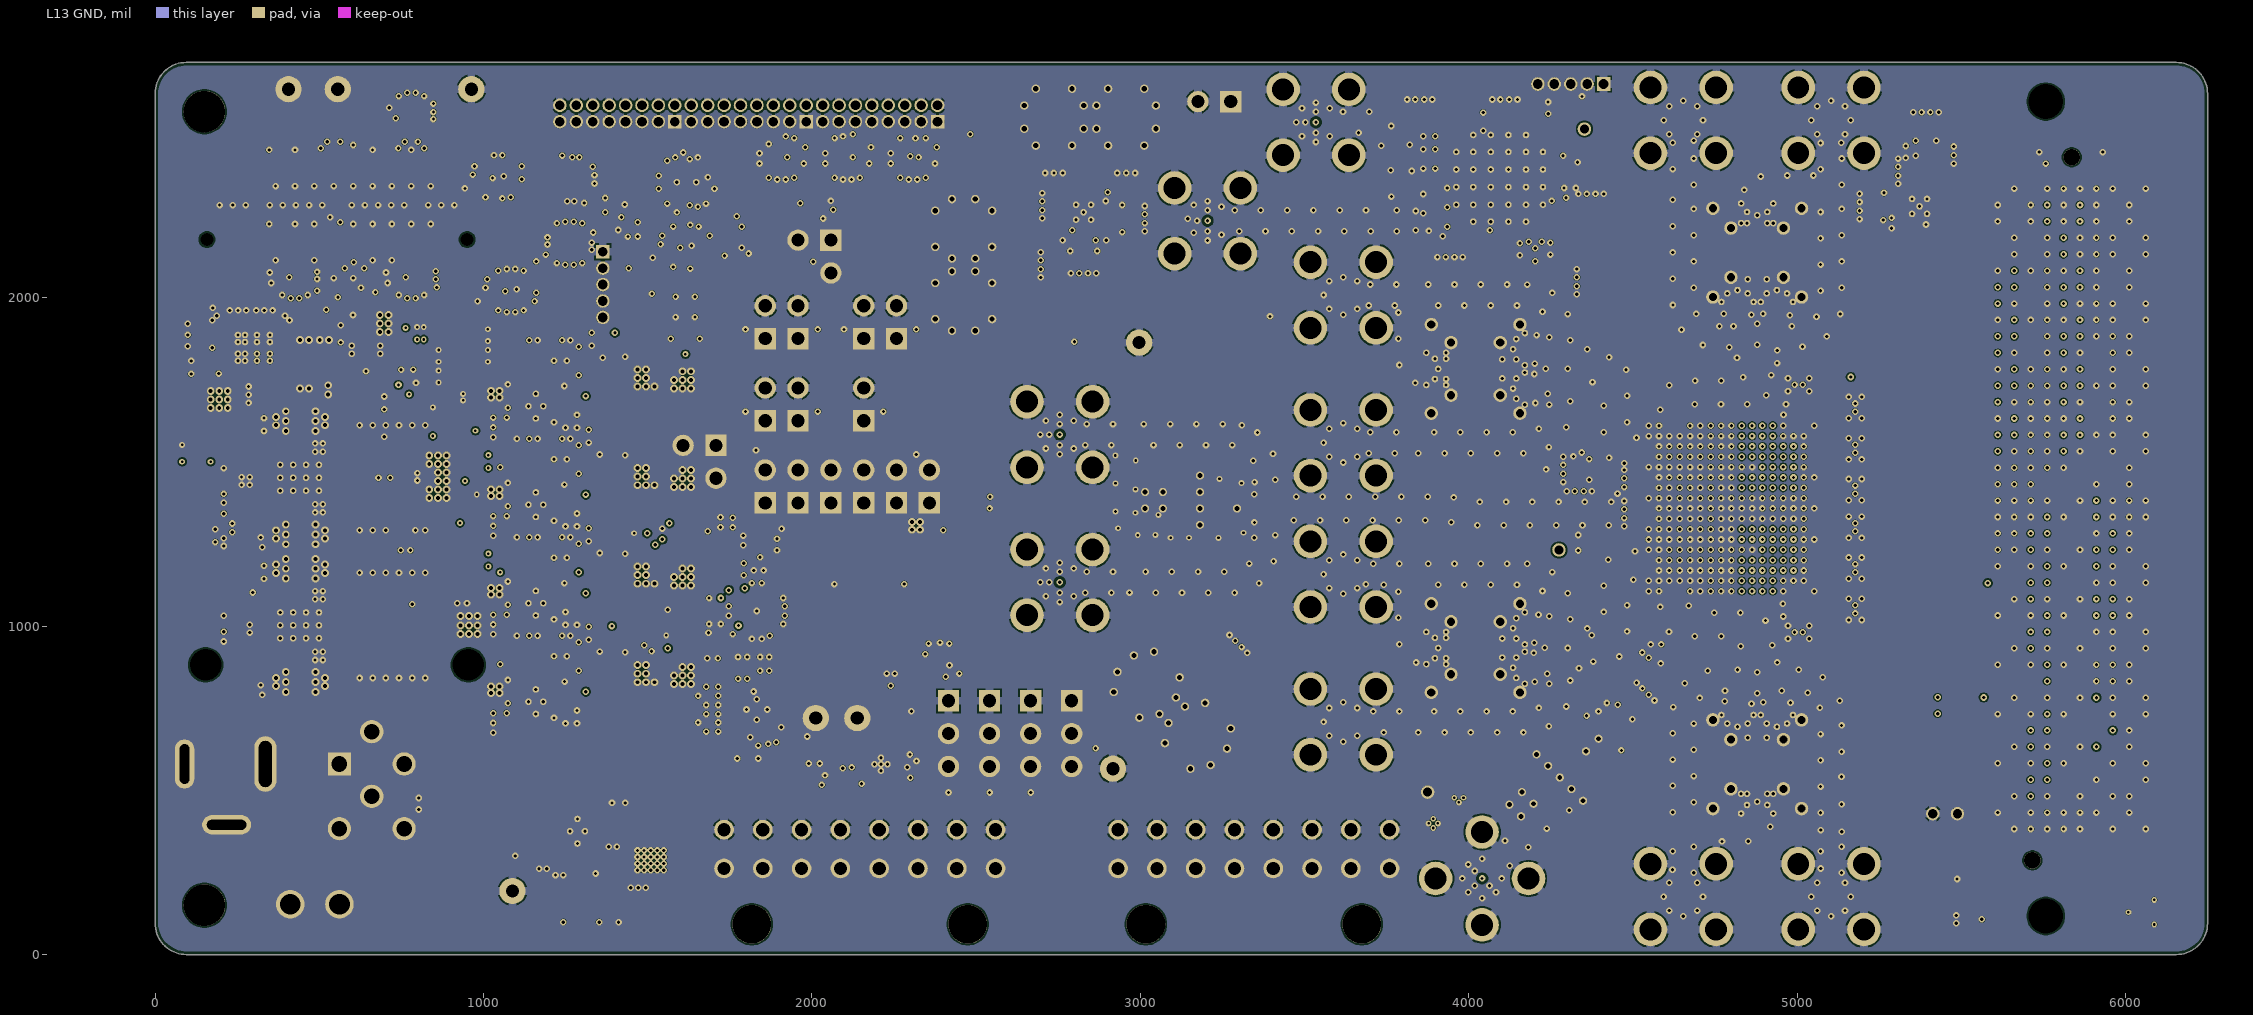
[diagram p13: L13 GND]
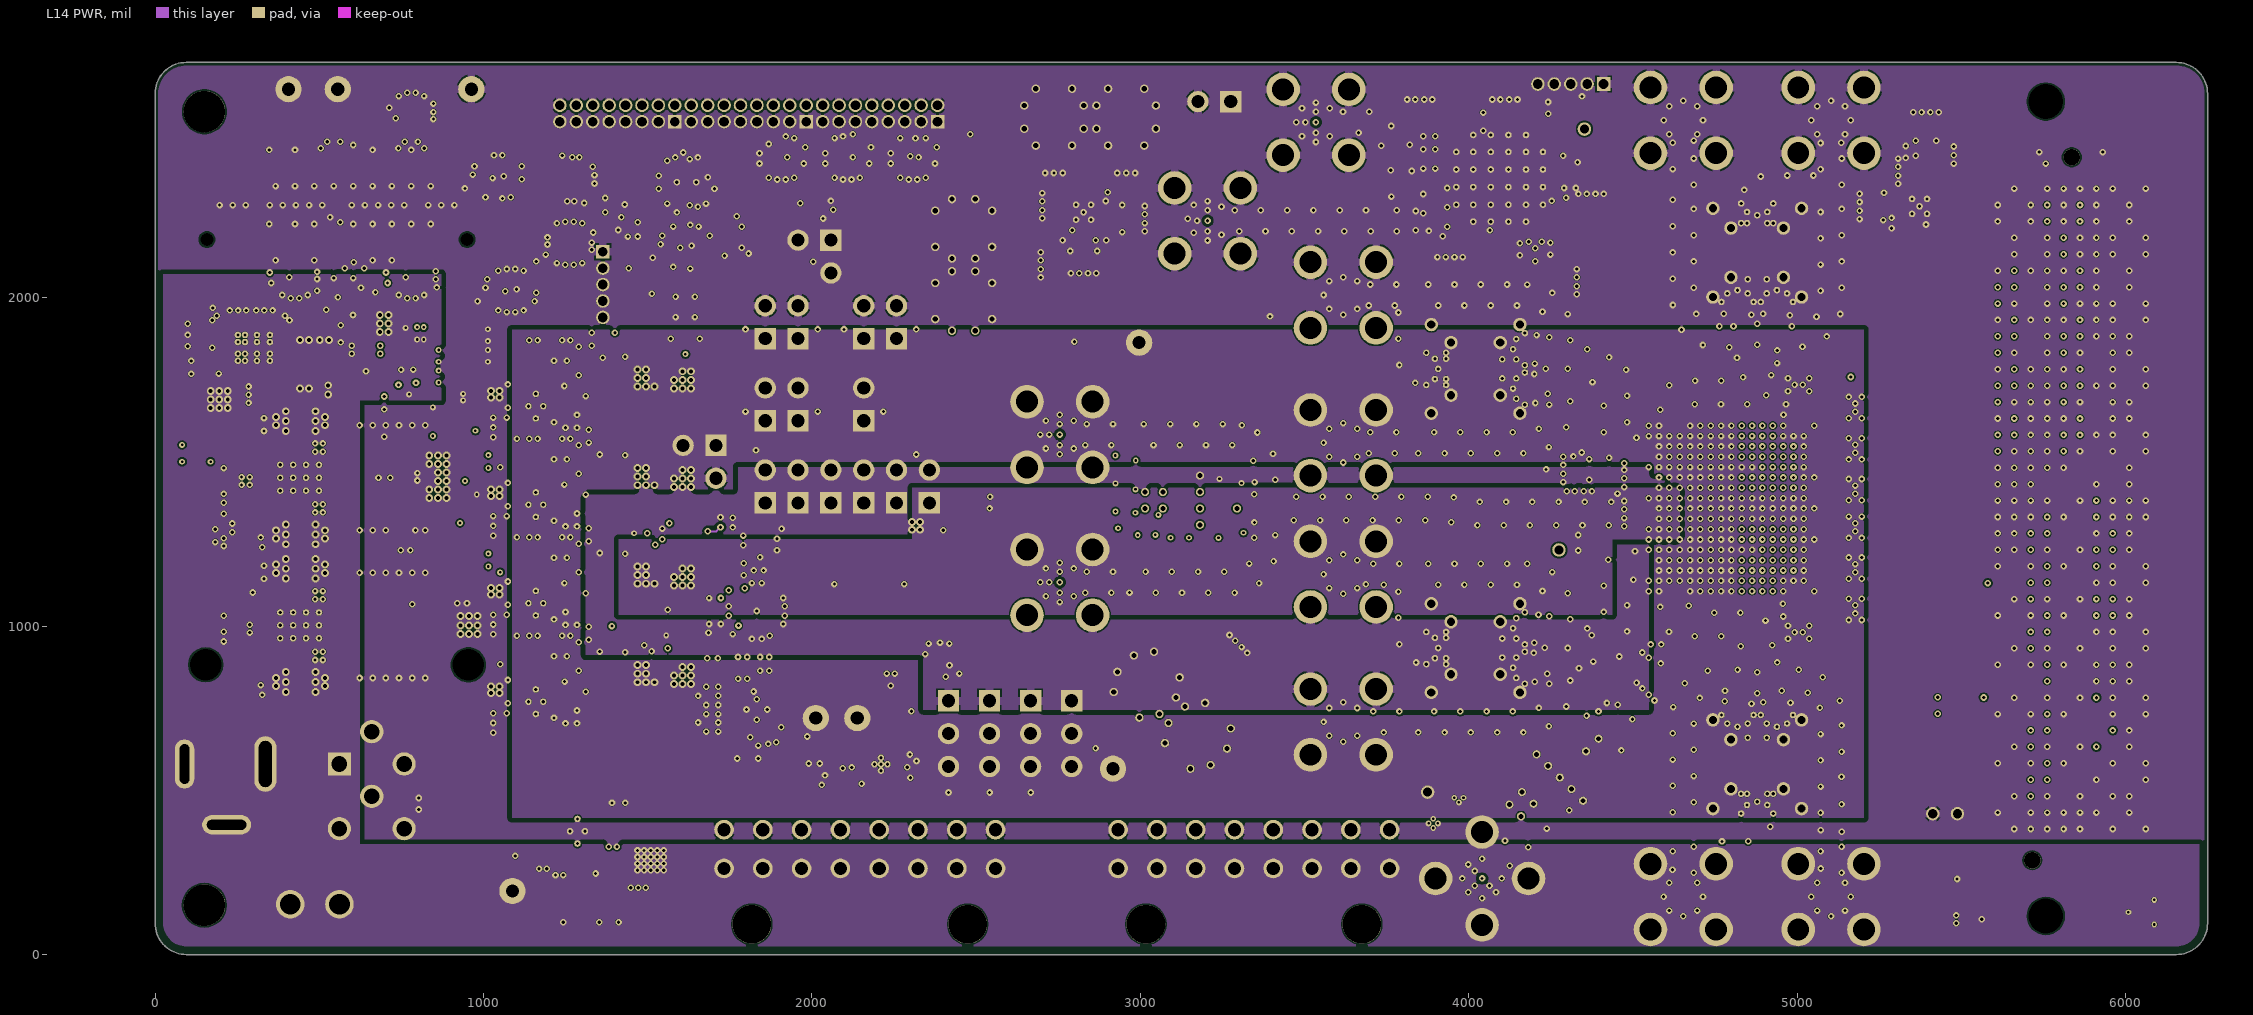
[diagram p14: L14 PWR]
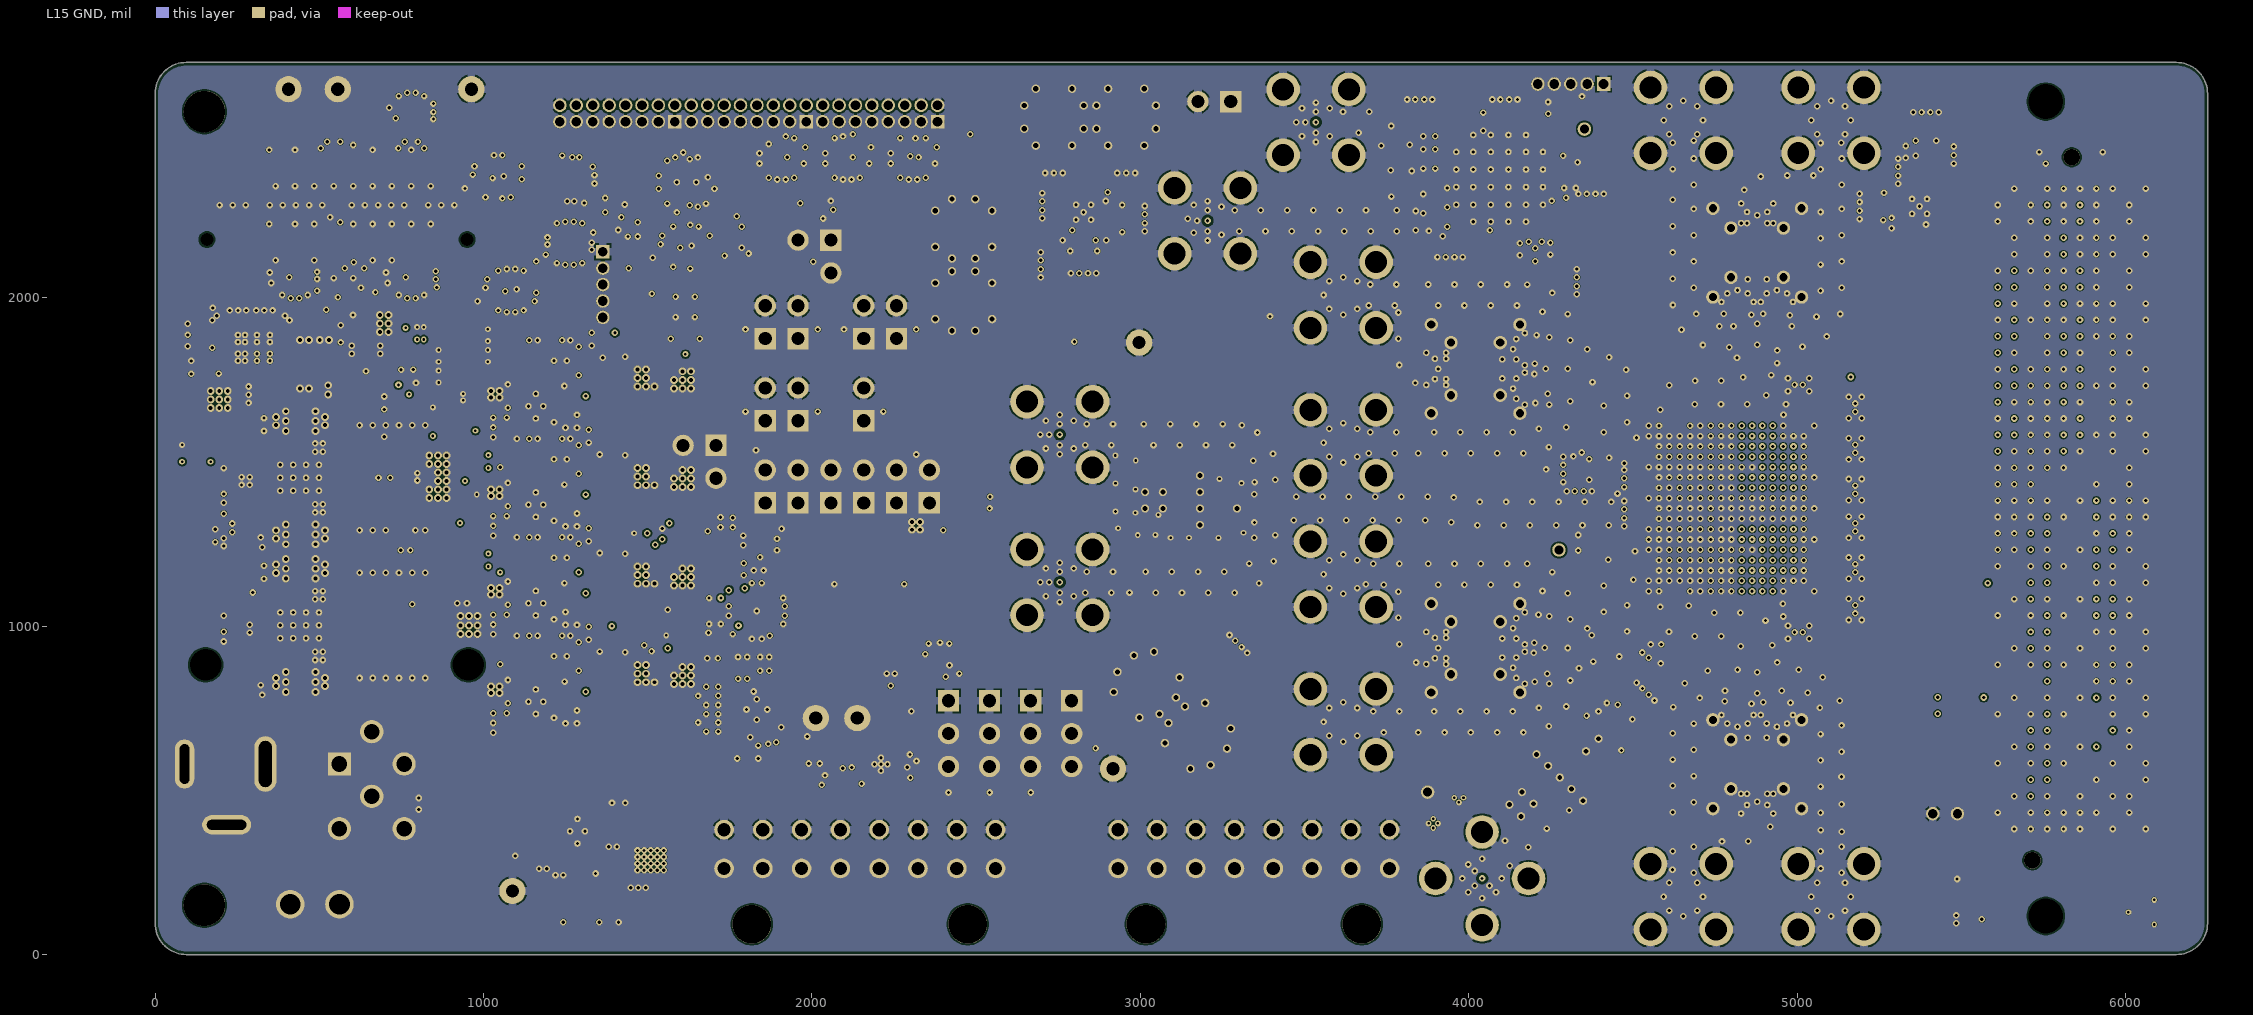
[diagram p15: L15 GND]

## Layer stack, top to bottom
Top Solder: solder mask 0.4, Solder Resist, Dk 3.5
Top Layer: signal copper 1.4
Dielectric 1: core 5.7, Megtron6, Dk 3.23
L2 GND: signal copper 1.4
Dielectric 3: prepreg 3, FR4-370HR, Dk 3.72
L3 PWR: signal copper 2.756
Dielectric 5: core 3, FR4-370HR, Dk 3.86
L4 GND: signal copper 1.4
Dielectric 7: prepreg 3, FR4-370HR, Dk 3.72
L5 PWR/SIG: signal copper 1.378
Dielectric 11: core 3, FR4-370HR, Dk 3.86
L6 GND: signal copper 1.378
Dielectric 15: prepreg 4.8, FR4-370HR, Dk 3.92
L7 SIGNAL: signal copper 0.689
Dielectric 9: prepreg 4.8, FR4-370HR, Dk 3.92
L8 GND: signal copper 1.378
Dielectric 13: prepreg 4.8, FR4-370HR, Dk 3.92
L9 GND: signal copper 1.378
Dielectric1: prepreg 4.8, FR4-370HR, Dk 3.92
L10 SIGNAL: signal copper 1.378
Dielectric 14: prepreg 4.8, FR4-370HR, Dk 3.92
L11 GND: signal copper 1.378
Dielectric 10: prepreg 4.8, FR4-370HR, Dk 3.92
L12 SIGNAL: signal copper 0.689
Dielectric 16: prepreg 4.8, FR4-370HR, Dk 3.92
L13 GND: signal copper 1.378
Dielectric 12: core 3, FR4-370HR, Dk 3.86
L14 PWR: signal copper 1.378
Dielectric 8: prepreg 3, FR4-370HR, Dk 3.72
L15 GND: signal copper 1.4
Dielectric 6: core 3, FR4-370HR, Dk 3.86
L16 PWR/SIG: signal copper 2.756
Dielectric 4: prepreg 3, FR4-370HR, Dk 3.72
L16 GND: signal copper 1.4
Dielectric 2: core 5.7, Megtron6, Dk 3.23
Bottom Layer: signal copper 1.4
Bottom Solder: solder mask 0.4, Solder Resist, Dk 3.5

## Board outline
0.01,95 0,2621.53 cw(c95,2621.53) 95,2716.53 6154.99,2716.54 cw(c6154.99,2621.54) 6249.99,2621.54 6250,95.01 cw(c6155,95.01) 6155,0.01 95.01,0 cw(c95.01,95)

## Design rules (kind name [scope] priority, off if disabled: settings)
AcuteAngle [All] p1: minimum=4.50000000000000E+0001 checktracksonly=TRUE
AssemblyTestPointUsage [All] p1: valid=2
BoardOutlineClearance BoardOutlineClearance_EdgeRFConnector [HasFootprint('FP-ELF040-001_SMA_EGDE_11p5_Launch')  or HasFootprint('FP-ELF040-001_SMA_EGDE_6p0_Launch') or HasFootprint('92_SK-U50-0-3')] p1: gap=14 ignorepadtopadclearanceinfootprint=FALSE
BoardOutlineClearance BoardOutlineClearance_Poly_GND [OnCopper and IsPoly and InNet('GND')] p2: gap=25 ignorepadtopadclearanceinfootprint=FALSE except(10: Poly-OutlineEdge)
BoardOutlineClearance BoardOutlineClearance_MountingHoles_1 [OnCopper and InComponentClass('Mounting Holes')] p3: gap=39.37 ignorepadtopadclearanceinfootprint=FALSE
BoardOutlineClearance BoardOutlineClearance_Poly [OnCopper and IsPoly] p4: gap=25 ignorepadtopadclearanceinfootprint=FALSE
BoardOutlineClearance [OnCopper and Not InComponentClass('Logo') and not InComponentClass('FiducialMark') and not InRegion(1000,500,4000,800) and not InPoly] p5: gap=25 ignorepadtopadclearanceinfootprint=FALSE except(24: Track-OutlineEdge)
Clearance "diff pairs" [InNetClass('LVDS_A') or InNetClass('LVDS_B')] p1: gap=5 ignorepadtopadclearanceinfootprint=TRUE except(4: Arc-SMDPad Arc-Via Track-SMDPad Track-Via SMDPad-Via; 8: Arc-Hole Track-Hole SMDPad-Hole THPad-Hole Via-Hole Fill-Hole Poly-Hole Region-Hole Text-Hole; 10: Arc-Arc Arc-Track Track-Track; 15: Arc-Fill Arc-Poly Arc-Region Track-Fill Track-Poly Track-Region Fill-Fill Fill-Poly Fill-Region Poly-Poly Poly-Region Region-Region)
Clearance Clearance_Poly_GND [InPolygon and InNet('GND')] p2: gap=5 ignorepadtopadclearanceinfootprint=TRUE except(15: Arc-Fill Arc-Poly Arc-Region Track-Fill Track-Poly Track-Region Fill-Fill Fill-Poly Fill-Region Poly-Poly Poly-Region Region-Region)
Clearance Clearance_Keepouts [((IsTrack Or IsArc) And Not InPoly) And IsFree and IsKeepOut vs ((IsTrack Or IsArc) And Not InPoly) And IsFree and IsKeepOut] p3: gap=0 ignorepadtopadclearanceinfootprint=FALSE
Clearance Clearance_Poly [InPolygon] p4: gap=5 ignorepadtopadclearanceinfootprint=TRUE except(15: Fill-Fill Fill-Poly Fill-Region Poly-Poly Poly-Region Region-Region)
Clearance Clearance_FiducialMark [IsKeepOut and InComponentClass('FiducialMark') vs IsPad and InComponentClass('FiducialMark')] p5: gap=0 ignorepadtopadclearanceinfootprint=FALSE
Clearance [All] p6: gap=5 ignorepadtopadclearanceinfootprint=TRUE except(4: Arc-Arc Arc-Track Arc-SMDPad Arc-THPad Arc-Via Arc-Fill Arc-Poly Arc-Region Arc-Text Track-Track Track-SMDPad Track-THPad Track-Via Track-Fill Track-Poly Track-Region Track-Text; 8: Arc-Hole Track-Hole; 9.2: SMDPad-SMDPad; 10: THPad-Fill THPad-Poly THPad-Region)
ComponentClearance "ComponentClearance Part Overlap" [All] p1: gap=0 collisioncheckmode=3 verticalgap=0 showdistances=FALSE
ComponentClearance ComponentClearance_MountingHoles_FiducialMarks [InComponentClass('Mounting Holes') vs InComponentClass('FiducialMark')] p2: gap=50 collisioncheckmode=3 verticalgap=10 showdistances=FALSE
ComponentClearance ComponentClearance_Shunt [InComponentClass('Header') vs InComponentClass('Shunt')] p3: gap=0 collisioncheckmode=3 verticalgap=0 showdistances=FALSE
ComponentClearance ComponentClearance_Logo [InComponentClass('Logo')] p4: gap=50 collisioncheckmode=3 verticalgap=10 showdistances=FALSE
ComponentClearance ComponentClearance_ScrewToNut [(HasFootprint('NY PMS 440 0025 PH')) vs (HasFootprint('Keystone_1902C'))] p5: gap=5 collisioncheckmode=3 verticalgap=10 showdistances=FALSE
ComponentClearance ComponentClearance_MountingHoles [InComponentClass('Mounting Holes')] p6: gap=200 collisioncheckmode=3 verticalgap=100000 showdistances=FALSE
ComponentClearance ComponentClearance_SmallPassives [HasFootprint('0201*') or HasFootprint('0402*') or HasFootprint('0508') or HasFootprint('0603*') or HasFootprint('0612') or HasFootprint('0805*') or HasFootprint('0815*') or HasFootprint('0830*') or HasFootprint('1206*') or HasFootprint('1210*') or HasFootprint('1808*') or HasFootprint('1812*') or HasFootprint('1825*') or HasFootprint('2010*') or HasFootprint('2220*') or HasFootprint('2225*') or HasFootprint('2512*') or HasFootprint('2728*') or HasFootprint('3518*') vs HasFootprint('0201*') or HasFootprint('0402*') or HasFootprint('0508') or HasFootprint('0603*') or HasFootprint('0612') or HasFootprint('0805*') or HasFootprint('0815*') or HasFootprint('0830*') or HasFootprint('1206*') or HasFootprint('1210*') or HasFootprint('1808*') or HasFootprint('1812*') or HasFootprint('1825*') or HasFootprint('2010*') or HasFootprint('2220*') or HasFootprint('2225*') or HasFootprint('2512*') or HasFootprint('2728*') or HasFootprint('3518*')] p7: gap=10 collisioncheckmode=3 verticalgap=10 showdistances=FALSE
ComponentClearance ComponentClearance_THtoSMT [IsThruComponent vs IsSMTComponent] p8: gap=20 collisioncheckmode=3 verticalgap=0 showdistances=FALSE
ComponentClearance ComponentClearance_THtoTH [IsThruComponent vs IsThruComponent] p9: gap=30 collisioncheckmode=3 verticalgap=30 showdistances=FALSE
ComponentClearance [All] p10: gap=10 collisioncheckmode=3 verticalgap=10 showdistances=FALSE
DiffPairsRouting DiffPairsRounting_LVDS_Bottom [OnLayer('Bottom Layer') And InNetClass('LVDS_A')] p1: maxlimit=10 minlimit=3 mostfreqgap=10 toplayer_prefgap=5 toplayer_minwidth=3 toplayer_maxwidth=15 toplayer_prefwidth=7.4 midlayer1_mingap=10 midlayer1_minwidth=15 midlayer1_maxwidth=15 midlayer1_prefwidth=15 midlayer2_mingap=10 midlayer2_minwidth=15 midlayer2_maxwidth=15 midlayer2_prefwidth=15 midlayer3_mingap=10 midlayer3_minwidth=15 midlayer3_maxwidth=15 midlayer3_prefwidth=15 midlayer4_mingap=10 midlayer4_minwidth=15 midlayer4_maxwidth=15 midlayer4_prefwidth=15 midlayer5_prefgap=6.5 midlayer5_minwidth=3 midlayer5_maxwidth=15 midlayer5_prefwidth=3.5 midlayer6_mingap=10 midlayer6_minwidth=15 midlayer6_maxwidth=15 midlayer6_prefwidth=15 midlayer7_mingap=10 midlayer7_minwidth=15 midlayer7_maxwidth=15 midlayer7_prefwidth=15 midlayer8_mingap=10 midlayer8_minwidth=15 midlayer8_maxwidth=15 midlayer8_prefwidth=15 midlayer9_mingap=10 midlayer9_minwidth=15 midlayer9_maxwidth=15 midlayer9_prefwidth=15 midlayer10_prefgap=6.5 midlayer10_minwidth=3 midlayer10_maxwidth=15 midlayer10_prefwidth=3.5 midlayer11_mingap=10 midlayer11_minwidth=15 midlayer11_maxwidth=15 midlayer11_prefwidth=15 midlayer12_mingap=10 midlayer12_minwidth=15 midlayer12_maxwidth=15 midlayer12_prefwidth=15 midlayer13_prefgap=6.5 midlayer13_minwidth=3 midlayer13_maxwidth=15 midlayer13_prefwidth=3.5 midlayer14_prefgap=6.5 midlayer14_minwidth=3 midlayer14_maxwidth=15 midlayer14_prefwidth=3.5 midlayer15_mingap=10 midlayer15_minwidth=15 midlayer15_maxwidth=15 midlayer15_prefwidth=15 midlayer16_mingap=10 midlayer16_minwidth=15 midlayer16_maxwidth=15 midlayer16_prefwidth=15 bottomlayer_mingap=4 bottomlayer_prefgap=4 bottomlayer_minwidth=5.8 bottomlayer_maxwidth=6.5 bottomlayer_prefwidth=6.5 maxuncoupledlength=500
DiffPairsRouting DiffPairsRouting_1 [InNetClass('SERDES_DP')] p2: maxlimit=10 minlimit=3 mostfreqgap=10 toplayer_mingap=4 toplayer_prefgap=4 toplayer_minwidth=6.3 toplayer_maxwidth=15 toplayer_prefwidth=6.3 midlayer1_mingap=10 midlayer1_minwidth=15 midlayer1_maxwidth=15 midlayer1_prefwidth=15 midlayer2_mingap=10 midlayer2_minwidth=15 midlayer2_maxwidth=15 midlayer2_prefwidth=15 midlayer3_mingap=10 midlayer3_minwidth=15 midlayer3_maxwidth=15 midlayer3_prefwidth=15 midlayer4_mingap=10 midlayer4_minwidth=15 midlayer4_maxwidth=15 midlayer4_prefwidth=15 midlayer5_mingap=10 midlayer5_minwidth=15 midlayer5_maxwidth=15 midlayer5_prefwidth=15 midlayer6_mingap=10 midlayer6_minwidth=15 midlayer6_maxwidth=15 midlayer6_prefwidth=15 midlayer7_mingap=10 midlayer7_minwidth=15 midlayer7_maxwidth=15 midlayer7_prefwidth=15 midlayer8_mingap=10 midlayer8_minwidth=15 midlayer8_maxwidth=15 midlayer8_prefwidth=15 midlayer9_mingap=10 midlayer9_minwidth=15 midlayer9_maxwidth=15 midlayer9_prefwidth=15 midlayer10_mingap=10 midlayer10_minwidth=15 midlayer10_maxwidth=15 midlayer10_prefwidth=15 midlayer11_mingap=10 midlayer11_minwidth=15 midlayer11_maxwidth=15 midlayer11_prefwidth=15 midlayer12_mingap=10 midlayer12_minwidth=15 midlayer12_maxwidth=15 midlayer12_prefwidth=15 midlayer13_prefgap=6.5 midlayer13_minwidth=3 midlayer13_maxwidth=15 midlayer13_prefwidth=3.5 midlayer14_mingap=10 midlayer14_minwidth=15 midlayer14_maxwidth=15 midlayer14_prefwidth=15 midlayer15_mingap=10 midlayer15_minwidth=15 midlayer15_maxwidth=15 midlayer15_prefwidth=15 midlayer16_mingap=10 midlayer16_minwidth=15 midlayer16_maxwidth=15 midlayer16_prefwidth=15 bottomlayer_mingap=4 bottomlayer_maxgap=4 bottomlayer_prefgap=4 bottomlayer_minwidth=6.3 bottomlayer_maxwidth=6.3 bottomlayer_prefwidth=6.3 maxuncoupledlength=500
DiffPairsRouting [All] p3: maxlimit=10 minlimit=3 mostfreqgap=10 toplayer_prefgap=5 toplayer_minwidth=3 toplayer_maxwidth=15 toplayer_prefwidth=7.4 midlayer1_mingap=10 midlayer1_minwidth=15 midlayer1_maxwidth=15 midlayer1_prefwidth=15 midlayer2_mingap=10 midlayer2_minwidth=15 midlayer2_maxwidth=15 midlayer2_prefwidth=15 midlayer3_mingap=10 midlayer3_minwidth=15 midlayer3_maxwidth=15 midlayer3_prefwidth=15 midlayer4_mingap=10 midlayer4_minwidth=15 midlayer4_maxwidth=15 midlayer4_prefwidth=15 midlayer5_prefgap=6.5 midlayer5_minwidth=3 midlayer5_maxwidth=15 midlayer5_prefwidth=3.5 midlayer6_mingap=10 midlayer6_minwidth=15 midlayer6_maxwidth=15 midlayer6_prefwidth=15 midlayer7_mingap=10 midlayer7_minwidth=15 midlayer7_maxwidth=15 midlayer7_prefwidth=15 midlayer8_mingap=10 midlayer8_minwidth=15 midlayer8_maxwidth=15 midlayer8_prefwidth=15 midlayer9_mingap=10 midlayer9_minwidth=15 midlayer9_maxwidth=15 midlayer9_prefwidth=15 midlayer10_prefgap=6.5 midlayer10_minwidth=3 midlayer10_maxwidth=15 midlayer10_prefwidth=3.5 midlayer11_mingap=10 midlayer11_minwidth=15 midlayer11_maxwidth=15 midlayer11_prefwidth=15 midlayer12_mingap=10 midlayer12_minwidth=15 midlayer12_maxwidth=15 midlayer12_prefwidth=15 midlayer13_prefgap=6.5 midlayer13_minwidth=3 midlayer13_maxwidth=15 midlayer13_prefwidth=3.5 midlayer14_prefgap=6.5 midlayer14_minwidth=3 midlayer14_maxwidth=15 midlayer14_prefwidth=3.5 midlayer15_mingap=10 midlayer15_minwidth=15 midlayer15_maxwidth=15 midlayer15_prefwidth=15 midlayer16_mingap=10 midlayer16_minwidth=15 midlayer16_maxwidth=15 midlayer16_prefwidth=15 bottomlayer_prefgap=5 bottomlayer_minwidth=3 bottomlayer_maxwidth=15 bottomlayer_prefwidth=7.4 maxuncoupledlength=500
FabricationTestPointUsage TestPointUsage [All] p1: valid=2 allowmultiple=FALSE
FabricationTestpoint Testpoint [All] p1: side=3 testpointundercomponent=TRUE minsize=40 maxsize=100 preferedsize=60 minholesize=0 maxholesize=40 preferedholesize=32 testpointgrid=1 allowsidetop=TRUE allowsidebottom=TRUE usegrid=TRUE gridtolerance=0.01
FanoutControl Fanout_LCC [IsLCC] p1: bgadir=Out bgaviamode=Centered fanoutstyle=Auto fanoutdirection=Alternating viagrid=1 // Fanout_LCC (Default Rule)
FanoutControl Fanout_BGA [IsBGA] p2: bgadir=Out bgaviamode=Centered fanoutstyle=Auto fanoutdirection=Alternating viagrid=1 // Fanout_BGA (Default Rule)
FanoutControl Fanout_Default [All] p4: bgadir=Out bgaviamode=Centered fanoutstyle=Auto fanoutdirection=Alternating viagrid=1 // Fanout_Default (Default Rule)
FanoutControl Fanout_Small [(CompPinCount < 5)] p5: bgadir=Out bgaviamode=Centered fanoutstyle=Auto fanoutdirection=OutThenIn viagrid=1 // Fanout_Small (Default Rule)
HoleSize [All] p1: absolutevalues=TRUE maxlimit=251 minlimit=7.87 maxpercent=80.000 minpercent=20.000
HoleToHoleClearance [All] p1: gap=8 allowstackedmicrovias=TRUE
MatchedLengths "LVDS-B Intra-Pair" [InNetClass('LVDS_B')] p1: tolerance=2 checknetsindiffpair=TRUE checkdiffpairvsdiffpair=FALSE checkxsignals=FALSE checkothers=FALSE usedelayunits=TRUE delaytolerance=20.000000
MatchedLengths "LVDS-B Inter-Pair" [InxSignalClass('LVDS_B_xSignals_U1_J29')] p2: tolerance=2 checknetsindiffpair=FALSE checkdiffpairvsdiffpair=TRUE checkxsignals=TRUE checkothers=TRUE usedelayunits=TRUE delaytolerance=100.000000 targetsourcename=DCLKB_P_PP1
MatchedLengths "LVDS-A Intra-Pair" [InNetClass('LVDS_A')] p3: tolerance=2 checknetsindiffpair=TRUE checkdiffpairvsdiffpair=FALSE checkxsignals=FALSE checkothers=FALSE usedelayunits=TRUE delaytolerance=20.000000
MatchedLengths "LVDS-A Inter-Pair" [InxSignalClass('LVDSA_xSignals_U1_J29')] p4: tolerance=2 checknetsindiffpair=FALSE checkdiffpairvsdiffpair=TRUE checkxsignals=TRUE checkothers=TRUE usedelayunits=TRUE delaytolerance=100.000000 targetsourcename=DCLKA_P_PP1
MinimumAnnularRing MinimumAnnularRing_ThermalPadVias [IsVia and InAnyComponent] p1: minimumring=0
MinimumAnnularRing [OnLayer('Top Layer') or OnLayer('Bottom Layer')] p2: minimumring=5
MinimumSolderMaskSliver MinimumSolderMaskSliver_Logo [InComponentClass('Logo') vs InComponentClass('Logo')] p1: minsoldermaskwidth=0.7
MinimumSolderMaskSliver [All] p2: minsoldermaskwidth=3
PlaneConnect [All] p1: planeconnectstyle=Relief reliefexpansion=10 reliefentries=4 reliefconductorwidth=10 reliefairgap=10
PolygonConnect "PolygonConnect Power Pad VIA" [HoleDiameter <= 25] p1: connectstyle=Direct reliefconductorwidth=25 reliefentries=4 polygonreliefangle="45 Angle" airgapwidth=5
PolygonConnect [All] p2: thpad.connectstyle=Relief thpad.reliefconductorwidth=25 thpad.reliefentries=4 thpad.polygonreliefangle="90 Angle" thpad.airgapwidth=5 smdpad.connectstyle=Direct smdpad.reliefconductorwidth=10 smdpad.reliefentries=4 smdpad.polygonreliefangle="90 Angle" smdpad.airgapwidth=10 via.connectstyle=Direct via.reliefconductorwidth=10 via.reliefentries=4 via.polygonreliefangle="90 Angle" via.airgapwidth=10
RoutingVias ThermalPadVias [IsVia and InAnyComponent] p1: holewidth=7.87 width=19.68 viastyle="Through Hole" minholewidth=6 minwidth=16 maxholewidth=65 maxwidth=65
RoutingVias [All] p2: holewidth=16 width=34 viastyle="Through Hole" minholewidth=6 minwidth=16 maxholewidth=40 maxwidth=65
SilkToBoardRegionClearance [Not ((IsComment or IsDesignator) And (Hide <> 'False')) and not InRegion(1000,500,4000,800)] p1:
SilkToSilkClearance SilkToSilkClearance_Pb-FreeLogo [(HasFootprint('Pb-Free_Overlay_Medium') OR HasFootprint('Pb-Free_Overlay_Small')) vs (HasFootprint('Pb-Free_Overlay_Medium') OR HasFootprint('Pb-Free_Overlay_Small'))] p1: silktosilkclearance=0
SilkToSilkClearance [All] p2: silktosilkclearance=3
SilkToSolderMaskClearance SilkToComponentPadClearance [(IsPad or IsFill or IsRegion) and InAnycomponent] p1: minsilkscreentomaskgap=3 clearancetoexposedcopper=TRUE
SilkToSolderMaskClearance "Silk to Solder Mask Opening" [All] p2: minsilkscreentomaskgap=0 clearancetoexposedcopper=FALSE
SolderMaskExpansion [All] p1: expansion=1.97 istentingtop=FALSE
SupplyNets "Schematic Supply Nets_46" [InNet('3p3V_AUX')] p1: voltage=0.000
SupplyNets "Schematic Supply Nets_45" [InNet('DVDD09_uFit_GND_SNS')] p2: voltage=0.000
SupplyNets "Schematic Supply Nets_44" [InNet('CLKVDD12_SENSE')] p3: voltage=0.000
SupplyNets "Schematic Supply Nets_43" [InNet('AVDD12')] p4: voltage=0.000
SupplyNets "Schematic Supply Nets_42" [InNet('DVDD09_GND_SENSE')] p5: voltage=0.000
SupplyNets "Schematic Supply Nets_41" [InNet('AVDD12_IN')] p6: voltage=0.000
SupplyNets "Schematic Supply Nets_40" [InNet('CLKVDD12')] p7: voltage=0.000
SupplyNets "Schematic Supply Nets_39" [InNet('CLKVDD12_OUT')] p8: voltage=0.000
SupplyNets "Schematic Supply Nets_38" [InNet('DVDD09_uFit_SNS')] p9: voltage=0.000
SupplyNets "Schematic Supply Nets_37" [InNet('AVDD18_uFit_SNS')] p10: voltage=0.000
SupplyNets "Schematic Supply Nets_36" [InNet('CLKVDD18_I2C_SENSE')] p11: voltage=0.000
SupplyNets "Schematic Supply Nets_35" [InNet('VADJ')] p12: voltage=0.000
SupplyNets "Schematic Supply Nets_34" [InNet('CLKVDD12_uFit')] p13: voltage=0.000
SupplyNets "Schematic Supply Nets_33" [InNet('CLKVDD18_IN')] p14: voltage=0.000
SupplyNets "Schematic Supply Nets_32" [InNet('GPIOVADJ')] p15: voltage=0.000
SupplyNets "Schematic Supply Nets_31" [InNet('CLKVDD18_SENSE')] p16: voltage=0.000
SupplyNets "Schematic Supply Nets_30" [InNet('AVDD12_SENSE')] p17: voltage=0.000
SupplyNets "Schematic Supply Nets_29" [InNet('AVDD18')] p18: voltage=0.000
SupplyNets "Schematic Supply Nets_28" [InNet('GND')] p19: voltage=0.000
SupplyNets "Schematic Supply Nets_27" [InNet('AVDD18_I2C_SENSE')] p20: voltage=0.000
SupplyNets "Schematic Supply Nets_26" [InNet('CLKVDD18_uFit_SNS')] p21: voltage=0.000
SupplyNets "Schematic Supply Nets_25" [InNet('DVDD09_SENSE')] p22: voltage=0.000
SupplyNets "Schematic Supply Nets_24" [InNet('DVDDMEM09')] p23: voltage=0.000
SupplyNets "Schematic Supply Nets_23" [InNet('CLKVDD18_uFit')] p24: voltage=0.000
SupplyNets "Schematic Supply Nets_22" [InNet('AVDD18_SENSE')] p25: voltage=0.000
SupplyNets "Schematic Supply Nets_21" [InNet('CLKVDD18')] p26: voltage=0.000
SupplyNets "Schematic Supply Nets_20" [InNet('3p3V_Utility')] p27: voltage=0.000
SupplyNets "Schematic Supply Nets_19" [InNet('CLKVDD12_uFit_SNS')] p28: voltage=0.000
SupplyNets "Schematic Supply Nets_18" [InNet('CLKVDD12_IN')] p29: voltage=0.000
SupplyNets "Schematic Supply Nets_17" [InNet('AVDD18_uFit')] p30: voltage=0.000
SupplyNets "Schematic Supply Nets_16" [InNet('AVDD12_uFit')] p31: voltage=0.000
SupplyNets "Schematic Supply Nets_15" [InNet('CLKVDD18_OUT')] p32: voltage=0.000
SupplyNets "Schematic Supply Nets_14" [InNet('DVDD09')] p33: voltage=0.000
SupplyNets "Schematic Supply Nets_13" [InNet('DVDD09_I2C_GND_SENSE')] p34: voltage=0.000
SupplyNets "Schematic Supply Nets_12" [InNet('2p3V')] p35: voltage=0.000
SupplyNets "Schematic Supply Nets_11" [InNet('3p3V')] p36: voltage=0.000
SupplyNets "Schematic Supply Nets_10" [InNet('DVDD09_I2C_SENSE')] p37: voltage=0.000
SupplyNets "Schematic Supply Nets_9" [InNet('AVDD12_OUT')] p38: voltage=0.000
SupplyNets "Schematic Supply Nets_8" [InNet('GPIOVDD')] p39: voltage=0.000
SupplyNets "Schematic Supply Nets_7" [InNet('12V')] p40: voltage=0.000
SupplyNets "Schematic Supply Nets_6" [InNet('AVDD12_I2C_SENSE')] p41: voltage=0.000
SupplyNets "Schematic Supply Nets_5" [InNet('AVDD12_uFit_SNS')] p42: voltage=0.000
SupplyNets "Schematic Supply Nets_4" [InNet('DVDD09_IN')] p43: voltage=0.000
SupplyNets "Schematic Supply Nets_3" [InNet('AVDD18_OUT')] p44: voltage=0.000
SupplyNets "Schematic Supply Nets_2" [InNet('CLKVDD12_I2C_SENSE')] p45: voltage=0.000
SupplyNets "Schematic Supply Nets_1" [InNet('DVDD09_uFit')] p46: voltage=0.000
SupplyNets "Schematic Supply Nets" [InNet('AVDD18_IN')] p47: voltage=0.000
UnRoutedNet [All] p1: checkbadconnections=TRUE
Width [All] p1: maxlimit=100 minlimit=4 preferedwidth=11.5 toplayer_prefwidth=12.1 midlayer1_prefwidth=6 midlayer2_prefwidth=4 midlayer3_prefwidth=6 midlayer4_prefwidth=6 midlayer5_prefwidth=4 midlayer6_prefwidth=6 midlayer7_prefwidth=4 midlayer8_prefwidth=4 midlayer10_prefwidth=4 midlayer13_prefwidth=4 bottomlayer_prefwidth=12.1 minimp=50.000000 maximp=50.000000 favimp=50.000000 checkconnectedcopper=TRUE
13 further rules are at their usual default settings.

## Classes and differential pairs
component class ADC34RF7x_Power_Sequencer: C184 C187 C188 C189 R224 R225 R226 U62 U63
net class LVDS_A: DCLKA_N DCLKA_P FCLKA_N FCLKA_P LVDS12A_N LVDS12A_P LVDSA0_N LVDSA0_P LVDSA1_N LVDSA1_P LVDSA2_N LVDSA2_P LVDSA3_N LVDSA3_P LVDSA4_N LVDSA4_P LVDSA5_N LVDSA5_P LVDSA6_N LVDSA6_P LVDSA7_N LVDSA7_P LVDSA8_N LVDSA8_P LVDSA9_N LVDSA9_P LVDSA10_N LVDSA10_P LVDSA11_N LVDSA11_P LVDSA12_N LVDSA12_P LVDSA13_N LVDSA13_P LVDSA14_N LVDSA14_P LVDSA15_N LVDSA15_P
net class SERDES_DP: ADC_JESDCLK_N ADC_JESDCLK_P DOUT0_ADC_N DOUT0_ADC_P DOUT0_FMC_N DOUT0_FMC_P DOUT1_ADC_N DOUT1_ADC_P DOUT1_FMC_N DOUT1_FMC_P DOUT2_ADC_N DOUT2_ADC_P DOUT2_FMC_N DOUT2_FMC_P DOUT3_ADC_N DOUT3_ADC_P DOUT3_FMC_N DOUT3_FMC_P DOUT4_ADC_N DOUT4_ADC_P DOUT4_FMC_N DOUT4_FMC_P DOUT5_ADC_N DOUT5_ADC_P DOUT5_FMC_N DOUT5_FMC_P DOUT6_ADC_N DOUT6_ADC_P DOUT6_FMC_N DOUT6_FMC_P DOUT7_ADC_N DOUT7_ADC_P DOUT7_FMC_N DOUT7_FMC_P
net class "Power sequencing": NetR131_1 NetR137_1 NetR143_1 NetR149_1 PG-3p3V_Util PG-DVDD09 PG-switcher
net class Power_Switcher_2p3V: 2p3V Switcher_2p3V
net class Power_DVDD09: DVDD09 DVDD09_IN
net class Power_CLKVDD18: CLKVDD18 CLKVDD18_IN CLKVDD18_OUT
net class Power_CLKVDD12: CLKVDD12 CLKVDD12_IN CLKVDD12_OUT
net class Power_AVDD18: AVDD18 AVDD18_IN AVDD18_OUT
net class Power_AVDD12: AVDD12 AVDD12_IN AVDD12_OUT
net class Power_3p3V_Utility: 3p3V 3p3V_Utility NetC130_1
net class Margining: NetC108_1 NetC109_1 NetC122_1 NetC124_1 NetR132_1 NetR136_1 NetR138_1 NetR142_1 NetR144_2 NetR148_1 NetR150_2 NetR154_1
net class LVDS_B: DCLKB_N DCLKB_P FCLKB_N FCLKB_P LVDSB0_N LVDSB0_P LVDSB1_N LVDSB1_P LVDSB2_N LVDSB2_P LVDSB3_N LVDSB3_P LVDSB4_N LVDSB4_P LVDSB5_N LVDSB5_P LVDSB6_N LVDSB6_P LVDSB7_N LVDSB7_P LVDSB8_N LVDSB8_P LVDSB9_N LVDSB9_P LVDSB10_N LVDSB10_P LVDSB11_N LVDSB11_P LVDSB12_N LVDSB12_P LVDSB13_N LVDSB13_P LVDSB14_N LVDSB14_P LVDSB15_N LVDSB15_P
net class I2C: SCL SCL0 SCL1 SCL2 SCL3 SCL4 SDA SDA0 SDA1 SDA2 SDA3 SDA4
net class "FPGA MGT REFCLK": MGTREFCLK0_LMK_N MGTREFCLK0_LMK_P MGTREFCLK1_FMC_N MGTREFCLK1_FMC_P
net class "FPGA CORECLK": LMK_CORECLK_N LMK_CORECLK_P
component class ADC34RF7x_USB_RevA: J28 R66 R67 R68 R69 R70 R78 R82 R185 R186 R207 TP3 TP6 TP7 TP8 U12 U14
component class ADC34RF7x_uFit_Power: J43 J44 R41 R42 R167 R168 R169 R170 R171 R172 R173 R174 R197 R198
component class ADC34RF7x_SYSREF_FPGA_MUX_RevA: C59 C61 C62 C63 C64 C65 C68 C75 C99 C100 C101 C256 C258 C259 C260 C261 C262 C263 C264 C265 J32 J33 J34 J35 J36 J37 J38 J39 J40 R155 R156 R157 R158 R159 R160 R161 R162 R163 R164 R165 R175 R176 R177 R178 R188 R189 R190 R191 R192 R193 R194 R195 R196 R204 R205 R208 R209 R210 SH-J34 SH-J38 SH-J39 SH-J40 T6 U52 U53 U54 U55 U56
component class ADC34RF7x_Power4_RevA: C122 C124 C242 C243 C244 C247 C248 C249 C250 C251 C254 C255 FB8 FB9 FB10 FB11 R143 R144 R145 R146 R147 R148 R149 R150 R151 R152 R153 R154 R233 R234 R235 R236 U46 U47 U48 U49 U50 U51 U67 U68
component class ADC34RF7x_Power3_RevA: C108 C109 C228 C229 C230 C233 C235 C236 C237 C240 C241 FB2 FB3 FB6 FB7 R131 R132 R133 R134 R135 R136 R137 R138 R139 R140 R141 R142 R229 R230 R231 R232 U40 U41 U42 U43 U44 U45 U65 U66
component class ADC34RF7x_Power2_RevA: C171 C172 C173 C174 C206 C207 C208 C209 C213 C214 C215 C216 C217 C218 C219 C220 C221 C222 C223 C224 C225 C226 C227 FB4 FB5 NT6 NT7 R118 R119 R120 R121 R122 R123 R124 R125 R126 R127 R128 R129 R130 R206 R227 R228 U37 U38 U39 U64
component class ADC34RF7x_Power1_RevA: C58 C71 C74 C95 C96 C97 C98 C126 C128 C130 C131 C167 C170 C198 C199 C200 C201 C202 C203 C204 C205 D3 D4 D5 F1 F2 FB1 FC1 J31 PP1 PP2 Q1 R108 R109 R110 R111 R112 R113 R114 R115 R116 R117 R179 TP11 TP12 U29 U35 U36
component class ADC34RF7x_MUX_RevA: C182 J21 J22 J23 J24 J25 J26 J27 J45 R52 R53 R56 R57 R59 R60 R64 R65 R71 R72 R73 R74 R75 R187 R215 R216 SH-J24 SH-J25 SH-J26 SH-J27 SH-J45 U6 U7 U8 U10 U11 U61
component class ADC34RF7x_LVL_Shft_RevA: J30 PP3 R79 R88 R89 R90 R91 R202 R203 R237 R238 SH-J30 SW2 SW3 SW4 SW6 U9 U15 U16 U17 U18 U19 U20 U21 U22 U23 U24 U25
component class ADC34RF7x_LMK_RevA: C41 C42 C43 C44 C45 C46 C47 C48 C49 C50 C51 C52 C53 C54 C55 C56 C57 C66 C67 C70 C72 C73 J11 J12 PP4 R33 R34 R35 R36 R37 R38 R39 R40 R54 R55 R58 R61 R62 R63 R76 R77 R80 R81 R166 R181 U2
component class ADC34RF7x_I2C_Shunts_Margining: C94 C102 C103 C104 C106 C107 C175 C176 C177 C178 C179 C181 C183 C185 C186 C191 C192 D6 R92 R93 R94 R95 R96 R97 R98 R99 R100 R101 R102 R103 R104 R105 R106 R107 R211 R212 R213 R214 U5 U13 U26 U27 U28 U30 U31 U32 U33 U34 U57 U58 U59 U60
component class ADC34RF7x_FMC_RevA: D1 D2 J29 R83 R84 R85 R86 R87 R182 R183 R184 R199 R200 R201 R217 R218
component class ADC34RF7x_ADC_Power_RevA: C60 C105 C110 C111 C112 C113 C114 C115 C116 C117 C118 C119 C120 C121 C123 C125 C127 C129 C132 C133 C134 C135 C136 C137 C138 C139 C140 C141 C142 C143 C144 C145 C146 C147 C148 C149 C150 C151 C152 C153 C154 C155 C156 C157 C158 C159 C160 C161 C162 C163 C164 C165 C166 C168 C169 C180 J19 J20 NT1 NT2 NT3 NT4 NT5 NT8 R51 SH-J19 SH-J20 TP4 TP5
component class ADC34RF7x_ADC_Input_CD_RevA: C25 C26 C27 C28 C29 C30 C31 C32 C33 C34 C35 C36 C37 C38 C39 C40 J7 J8 J9 J10 R19 R20 R21 R22 R23 R24 R25 R26 R27 R28 R29 R30 R31 R32 T4 T5
component class ADC34RF7x_ADC_Dig_RevA: C69 C76 C77 C78 C79 C80 C81 C82 C83 C84 C85 C86 C87 C88 C89 C90 C91 C92 C93 J13 J14 J15 J16 J17 J18 J41 J42 PP5 R43 R44 R45 R46 R47 R48 R49 R50 R180 R219 R220 R221 R222 R223 SW1 TP9 TP10 U1 U3 U4
component class ADC34RF7x_Misc_RevA: !PCB1 FID1 FID2 FID3 H2 H4 LBL1 LOGO1 Logo2 Logo3 Logo4 Logo5 Logo6 Logo12 MP1 MP2 ZZ1 ZZ2 ZZ3 ZZ4
component class ADC34RF7x_ADC_Input_AB_RevA: C1 C2 C3 C4 C5 C6 C7 C8 C9 C10 C11 C12 C13 C14 C15 C16 C17 C18 C19 C20 C21 C22 C23 C24 J1 J2 J3 J4 J5 J6 R1 R2 R3 R4 R5 R6 R7 R8 R9 R10 R11 R12 R13 R14 R15 R16 R17 R18 T1 T2 T3
differential pair LVDS12A: +LVDS12A_P -LVDS12A_N
differential pair LVDSA15: +LVDSA15_P -LVDSA15_N
differential pair LVDSA14: +LVDSA14_P -LVDSA14_N
differential pair LVDSA13: +LVDSA13_P -LVDSA13_N
differential pair LVDSA12: +LVDSA12_P -LVDSA12_N
differential pair LVDSA11: +LVDSA11_P -LVDSA11_N
differential pair LVDSA10: +LVDSA10_P -LVDSA10_N
differential pair LVDSA9: +LVDSA9_P -LVDSA9_N
differential pair LVDSA8: +LVDSA8_P -LVDSA8_N
differential pair LVDSA7: +LVDSA7_P -LVDSA7_N
differential pair LVDSA6: +LVDSA6_P -LVDSA6_N
differential pair LVDSA5: +LVDSA5_P -LVDSA5_N
differential pair LVDSA4: +LVDSA4_P -LVDSA4_N
differential pair LVDSA3: +LVDSA3_P -LVDSA3_N
differential pair LVDSA2: +LVDSA2_P -LVDSA2_N
differential pair LVDSA1: +LVDSA1_P -LVDSA1_N
differential pair LVDSA0: +LVDSA0_P -LVDSA0_N
differential pair FCLKA: +FCLKA_P -FCLKA_N
differential pair DCLKA: +DCLKA_P -DCLKA_N
differential pair SMA_JESDCLKIN: +SMA_JESDCLKIN_P -SMA_JESDCLKIN_N
differential pair TSTAMP: +TSTAMP_P -TSTAMP_N
differential pair MGTREFCLK0_FMC: +MGTREFCLK0_FMC_P -MGTREFCLK0_FMC_N
differential pair ADC_JESDCLK_MGTREFCLK: +ADC_JESDCLK_MGTREFCLK_P -ADC_JESDCLK_MGTREFCLK_N
differential pair ADC_JESDCLK_CORECLK: +ADC_JESDCLK_CORECLK_P -ADC_JESDCLK_CORECLK_N
differential pair ADC_JESDCLKIN: +ADC_JESDCLKIN_P -ADC_JESDCLKIN_N
differential pair ADC_SYSREFOUT_1: +FPGA_SYSREF_P -FPGA_SYSREF_N
differential pair EXT_SYSREF: +EXT_SYSREF_P -EXT_SYSREF_N
differential pair MGTREFCLK1_FMC: +MGTREFCLK1_FMC_P -MGTREFCLK1_FMC_N
differential pair MGTREFCLK0_LMK: +MGTREFCLK0_LMK_P -MGTREFCLK0_LMK_N
differential pair LVDSB15: +LVDSB15_P -LVDSB15_N
differential pair LVDSB14: +LVDSB14_P -LVDSB14_N
differential pair LVDSB13: +LVDSB13_P -LVDSB13_N
differential pair LVDSB12: +LVDSB12_P -LVDSB12_N
differential pair LVDSB11: +LVDSB11_P -LVDSB11_N
differential pair LVDSB10: +LVDSB10_P -LVDSB10_N
differential pair LVDSB9: +LVDSB9_P -LVDSB9_N
differential pair LVDSB8: +LVDSB8_P -LVDSB8_N
differential pair LVDSB7: +LVDSB7_P -LVDSB7_N
differential pair LVDSB6: +LVDSB6_P -LVDSB6_N
differential pair LVDSB5: +LVDSB5_P -LVDSB5_N
differential pair LVDSB4: +LVDSB4_P -LVDSB4_N
differential pair LVDSB3: +LVDSB3_P -LVDSB3_N
differential pair LVDSB2: +LVDSB2_P -LVDSB2_N
differential pair LVDSB1: +LVDSB1_P -LVDSB1_N
differential pair LVDSB0: +LVDSB0_P -LVDSB0_N
differential pair LMK_CORECLK: +LMK_CORECLK_P -LMK_CORECLK_N
differential pair IND_ADC: +IND_ADC_P -IND_ADC_N
differential pair INC_ADC: +INC_ADC_P -INC_ADC_N
differential pair INB_ADC: +INB_ADC_P -INB_ADC_N
differential pair INA_ADC: +INA_ADC_P -INA_ADC_N
differential pair FPGA_SYSREF_LMK: +FPGA_SYSREF_LMK_P -FPGA_SYSREF_LMK_N
differential pair FCLKB: +FCLKB_P -FCLKB_N
differential pair DOUT7_FMC: +DOUT7_FMC_P -DOUT7_FMC_N
differential pair DOUT7_ADC: +DOUT7_ADC_P -DOUT7_ADC_N
differential pair DOUT6_FMC: +DOUT6_FMC_P -DOUT6_FMC_N
differential pair DOUT6_ADC: +DOUT6_ADC_P -DOUT6_ADC_N
differential pair DOUT5_FMC: +DOUT5_FMC_P -DOUT5_FMC_N
differential pair DOUT5_ADC: +DOUT5_ADC_P -DOUT5_ADC_N
differential pair DOUT4_FMC: +DOUT4_FMC_P -DOUT4_FMC_N
differential pair DOUT4_ADC: +DOUT4_ADC_P -DOUT4_ADC_N
differential pair DOUT3_FMC: +DOUT3_FMC_P -DOUT3_FMC_N
differential pair DOUT3_ADC: +DOUT3_ADC_P -DOUT3_ADC_N
differential pair DOUT2_FMC: +DOUT2_FMC_P -DOUT2_FMC_N
differential pair DOUT2_ADC: +DOUT2_ADC_P -DOUT2_ADC_N
differential pair DOUT1_FMC: +DOUT1_FMC_P -DOUT1_FMC_N
differential pair DOUT1_ADC: +DOUT1_ADC_P -DOUT1_ADC_N
differential pair DOUT0_FMC: +DOUT0_FMC_P -DOUT0_FMC_N
differential pair DOUT0_ADC: +DOUT0_ADC_P -DOUT0_ADC_N
differential pair DCLKB: +DCLKB_P -DCLKB_N
differential pair ADC_SYSREF: +ADC_SYSREF_P -ADC_SYSREF_N
differential pair ADC_SYSREFOUT: +ADC_SYSREFOUT_P -ADC_SYSREFOUT_N
differential pair ADC_SYSREF_LMK: +ADC_SYSREF_LMK_P -ADC_SYSREF_LMK_N
differential pair ADC_JESDCLK: +ADC_JESDCLK_P -ADC_JESDCLK_N
differential pair ADC_JESDCLKIN_LMK: +ADC_JESDCLKIN_LMK_P -ADC_JESDCLKIN_LMK_N
differential pair ADC_CLK: +ADC_CLK_P -ADC_CLK_N

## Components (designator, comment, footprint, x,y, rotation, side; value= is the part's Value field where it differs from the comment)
C1 "0201BB104KW160" 0201_cap#1 4838.37,835.2 r0 top value="0.1 uF"
C2 "0201BB104KW160" 0201_cap#1 4653.52,387.35 r270 top value="0.1 uF"
C3 "0201BB104KW160" 0201_cap#1 4849.4,824.18 r90 top value="0.1 uF"
C4 "0201BB104KW160" 0201_cap#1 4664.54,376.33 r0 top value="0.1 uF"
C5 "GRM033Z71C104KE14D" 0201_cap#1 4878.52,878.06 r90 top value="0.1 uF"
C6 "0201BB104KW160" 0201_cap#1 4907.64,824.18 r90 top value="0.1 uF"
C7 "0201BB104KW160" 0201_cap#1 4918.67,835.2 r0 top value="0.1 uF"
C8 "0201BB104KW160" 0201_cap#1 5103.52,387.35 r90 top value="0.1 uF"
C9 "0201BB104KW160" 0201_cap#1 4276.94,973.44 r270 top value="0.1 uF"
C10 "0201BB104KW160" 0201_cap#1 3829.08,1158.29 r180 top value="0.1 uF"
C11 "0201BB104KW160" 0201_cap#1 4265.91,962.41 r0 top value="0.1 uF"
C12 "0201BB104KW160" 0201_cap#1 3818.06,1147.27 r270 top value="0.1 uF"
C13 "GRM033Z71C104KE14D" 0201_cap#1 4319.8,933.29 r0 top value="0.1 uF"
C14 "0201BB104KW160" 0201_cap#1 4265.91,904.17 r0 top value="0.1 uF"
C15 "0201BB104KW160" 0201_cap#1 4276.94,893.15 r270 top value="0.1 uF"
C16 "0201BB104KW160" 0201_cap#1 3829.08,708.29 r0 top value="0.1 uF"
C17 "0201BB104KW160" 0201_cap#1 2966.02,1583.28 r180 bottom value="0.1 uF"
C18 "0201BB104KW160" 0201_cap#1 3379.28,1380.63 r270 bottom value="0.1 uF"
C19 "0201BB104KW160" 0201_cap#1 3368.26,1369.6 r0 bottom value="0.1 uF"
C20 "0201BB104KW160" 0201_cap#1 2955,1572.26 r270 bottom value="0.1 uF"
C21 "0201BB104KW160" 0201_cap#1 3058.02,1308.28 r0 bottom value="0.1 uF"
C22 "0201BB104KW160" 0201_cap#1 3368.26,1346.96 r0 bottom value="0.1 uF"
C23 "0201BB104KW160" 0201_cap#1 3379.28,1335.93 r270 bottom value="0.1 uF"
C24 "0201BB104KW160" 0201_cap#1 2966.02,1133.28 r0 bottom value="0.1 uF"
C25 "0201BB104KW160" 0201_cap#1 4918.69,1881.33 r180 top value="0.1 uF"
C26 "0201BB104KW160" 0201_cap#1 4907.67,1892.35 r270 top value="0.1 uF"
C27 "0201BB104KW160" 0201_cap#1 5103.54,2329.18 r90 top value="0.1 uF"
C28 "0201BB104KW160" 0201_cap#1 5092.52,2340.21 r180 top value="0.1 uF"
C29 "GRM033Z71C104KE14D" 0201_cap#1 4878.54,1838.47 r270 top value="0.1 uF"
C30 "0201BB104KW160" 0201_cap#1 4849.42,1892.35 r270 top value="0.1 uF"
C31 "0201BB104KW160" 0201_cap#1 4838.4,1881.33 r180 top value="0.1 uF"
C32 "0201BB104KW160" 0201_cap#1 4653.54,2329.18 r270 top value="0.1 uF"
C33 "0201BB104KW160" 0201_cap#1 4276.94,1823.41 r270 top value="0.1 uF"
C34 "0201BB104KW160" 0201_cap#1 3829.08,2008.27 r180 top value="0.1 uF"
C35 "0201BB104KW160" 0201_cap#1 4265.91,1812.39 r0 top value="0.1 uF"
C36 "0201BB104KW160" 0201_cap#1 3818.06,1997.24 r270 top value="0.1 uF"
C37 "GRM033Z71C104KE14D" 0201_cap#1 4319.8,1783.27 r0 top value="0.1 uF"
C38 "0201BB104KW160" 0201_cap#1 4265.91,1754.15 r0 top value="0.1 uF"
C39 "0201BB104KW160" 0201_cap#1 4276.94,1743.12 r270 top value="0.1 uF"
C40 "0201BB104KW160" 0201_cap#1 3829.08,1558.27 r0 top value="0.1 uF"
C41 "C0603X5R1E104K030BB" 0201_cap#1 3948.98,2275.08 r0 top value="0.1 uF"
C42 "C0603X5R1E104K030BB" 0201_cap#1 3920.96,2205 r270 top value="0.1 uF"
C43 "C0603X5R1E104K030BB" 0201_cap#1 3948.98,2334.13 r0 top value="0.1 uF"
C44 "C0603X5R1E104K030BB" 0201_cap#1 3879.94,2393.19 r180 bottom value="0.1 uF"
C45 "C0603X5R1E104K030BB" 0201_cap#1 3879.94,2452.24 r180 bottom value="0.1 uF"
C46 "C0603X5R1E104K030BB" 0201_cap#1 3879.94,2491.61 r180 bottom value="0.1 uF"
C47 "C0603X5R1E104K030BB" 0201_cap#1 4044.13,2539.78 r270 top value="0.1 uF"
C48 "C0603X5R1E104K030BB" 0201_cap#1 4308.44,2334.13 r0 bottom value="0.1 uF"
C49 "C0603X5R1E104K030BB" 0201_cap#1 4241.82,2577.91 r90 bottom value="0.1 uF"
C50 "C0603X5R1E104K030BB" 0201_cap#1 4066.99,2217.54 r90 top value="0.1 uF"
C51 "C0603X5R1E104K030BB" 0201_cap#1 4248.82,2149.41 r270 bottom value="0.1 uF"
C52 "C0603X5R1E104K030BB" 0201_cap#1 4156.08,2147.41 r270 bottom value="0.1 uF"
C53 "C0603X5R1E104K030BB" 0201_cap#1 3879.94,2293.26 r180 bottom value="0.1 uF"
C54 "C0603X5R1E104K030BB" 0201_cap#1 3879.94,2315.95 r180 bottom value="0.1 uF"
C55 "0201BB104KW160" 0201_cap#1 3808.91,2223.18 r90 bottom value="0.1 uF"
C56 "0201BB104KW160" 0201_cap#1 3745.84,2234.21 r180 bottom value="0.1 uF"
C57 "C0603X5R1E104K030BB" 0201_cap#1 3879.94,2256.89 r0 bottom value="0.1 uF"
C58 "C1005X5R1E225K050BC" 0402L_cap#1 5562.52,87.31 r90 bottom value="2.2 uF"
C59 "C0603X5R1E104K030BB" 0201_cap#1 5378.8,2535.42 r270 bottom value="0.1 uF"
C60 "0402ZD106MAT2A" 0402L_cap#1 2294.13,1522.61 r180 bottom value="10 uF"
C61 "C0603X5R1E104K030BB" 0201_cap#1 2880.36,2175.32 r180 bottom value="0.1 uF"
C62 "C0603X5R1E104K030BB" 0201_cap#1 2779.27,2175.32 r0 bottom value="0.1 uF"
C63 "C0603X5R1E104K030BB" 0201_cap#1 5287.73,2326.08 r270 bottom value="0.1 uF"
C64 "C0603X5R1E104K030BB" 0201_cap#1 5406.15,2535.54 r270 bottom value="0.1 uF"
C65 "C0603X5R1E104K030BB" 0201_cap#1 4494.5,772.37 r225 bottom value="0.1 uF"
C66 "0201BB104KW160" 0201_cap#1 4041.46,2126.41 r270 bottom value="0.1 uF"
C67 "0201BB104KW160" 0201_cap#1 4018.81,2126.41 r270 bottom value="0.1 uF"
C68 "C0603X5R1E104K030BB" 0201_cap#1 4510.09,756.78 r225 bottom value="0.1 uF"
C69 "C1005X5R1H104K050BB" 0402L_cap#1 2322.68,740.77 r0 bottom value="0.1 uF"
C70 "C0603X5R1E104K030BB" 0201_cap#1 3879.94,2234.21 r180 bottom value="0.1 uF"
C71 "C2012X7R1H105K125AB" 0805L_cap#1 757.1,678.57 r90 bottom value="1 uF"
C72 "0603ZD106KAT2A" 0603L_cap 4271.84,2315.26 r135 top value="10 uF"
C73 "C0603X5R1E104K030BB" 0201_cap#1 4237.76,2295.44 r180 top value="0.1 uF"
C74 "C1005X6S1C225K050BC" 0402L_cap#1 5487.08,244.69 r90 bottom value="2.2 uF"
C75 "0201BB104KW160" 0201_cap#1 4344.08,676.37 r225 bottom value="0.1 uF"
C76 "0201BB104KW160" 0201_cap#1 4993.42,1025.28 r270 top value="0.1 uF"
C77 "0201BB104KW160" 0201_cap#1 5016.02,1025.28 r270 top value="0.1 uF"
C78 "0201BB104KW160" 0201_cap#1 5132.99,1039.85 r0 top value="0.1 uF"
C79 "0201BB104KW160" 0201_cap#1 5132.99,1062.45 r0 top value="0.1 uF"
C80 "0201BB104KW160" 0201_cap#1 5132.99,1165.24 r0 top value="0.1 uF"
C81 "0201BB104KW160" 0201_cap#1 5132.99,1187.83 r0 top value="0.1 uF"
C82 "0201BB104KW160" 0201_cap#1 5132.99,1289.73 r0 top value="0.1 uF"
C83 "0201BB104KW160" 0201_cap#1 5132.99,1312.32 r0 top value="0.1 uF"
C84 "0201BB104KW160" 0201_cap#1 5016.02,1691.26 r90 top value="0.1 uF"
C85 "0201BB104KW160" 0201_cap#1 4993.43,1691.26 r90 top value="0.1 uF"
C86 "0201BB104KW160" 0201_cap#1 5132.99,1654.09 r0 top value="0.1 uF"
C87 "0201BB104KW160" 0201_cap#1 5132.99,1676.69 r0 top value="0.1 uF"
C88 "0201BB104KW160" 0201_cap#1 5132.99,1528.7 r0 top value="0.1 uF"
C89 "0201BB104KW160" 0201_cap#1 5132.99,1551.3 r0 top value="0.1 uF"
C90 "0201BB104KW160" 0201_cap#1 5132.99,1404.21 r0 top value="0.1 uF"
C91 "0201BB104KW160" 0201_cap#1 5132.99,1426.81 r0 top value="0.1 uF"
C92 "0402ZD106MAT2A" 0402L_cap#1 4333.91,1253.94 r90 bottom value="10 uF"
C93 "C0603X5R1E104K030BB" 0201_cap#1 4595.28,1263.78 r180 bottom value="0.1 uF"
C94 "04026D104KAT4A" 0402L_cap#1 1837,616.52 r270 bottom value="0.1 uF"
C95 "C2012X7R1H105K125AB" 0805L_cap#1 1411.26,447.25 r270 bottom value="1 uF"
C96 "C2012X7R1H105K125AB" 0805L_cap#1 1396.26,343.08 r90 bottom value="1 uF"
C97 "CGA3E2X7R1H102K080AA" 0603L_cap 1181.14,272.71 r90 bottom value="0.001 uF"
C98 "CGA3E2X7R1H102K080AA" 0603L_cap 1231.03,253.77 r90 bottom value="0.001 uF"
C99 "0201BB104KW160" 0201_cap#1 4414.14,606.31 r225 bottom value="0.1 uF"
C100 "C0603X5R1E104K030BB" 0201_cap#1 2969.46,2255.27 r0 bottom value="0.1 uF"
C101 "C0603X5R1E104K030BB" 0201_cap#1 2969.45,2226.22 r0 bottom value="0.1 uF"
C102 "04026D104KAT4A" 0402L_cap#1 697.55,1679.56 r90 top value="0.1 uF"
C103 "04026D104KAT4A" 0402L_cap#1 1320.5,978.52 r270 bottom value="0.1 uF"
C104 "04026D104KAT4A" 0402L_cap#1 1320.5,1578.52 r270 bottom value="0.1 uF"
C105 "C0603X5R1E104K030BB" 0201_cap#1 4847.24,1374.02 r45 bottom value="0.1 uF"
C106 "04026D104KAT4A" 0402L_cap#1 1330.5,1873.52 r270 bottom value="0.1 uF"
C107 "04026D104KAT4A" 0402L_cap#1 1320.5,1278.52 r270 bottom value="0.1 uF"
C108 "C1005X5R1A475K050BE" 0402L_cap#1 1249.61,1623.35 r270 top value="4.7 uF"
C109 "C1005X5R1A475K050BE" 0402L_cap#1 1249.61,1323.35 r270 top value="4.7 uF"
C110 "C0603X5R1E104K030BB" 0201_cap#1 4941.73,1342.52 r135 bottom value="0.1 uF"
C111 "C0603X5R1E104K030BB" 0201_cap#1 4910.24,1342.52 r135 bottom value="0.1 uF"
C112 "C0603X5R1E104K030BB" 0201_cap#1 4878.74,1374.02 r45 bottom value="0.1 uF"
C113 "GRM033R61A105ME44D" 0201_cap#1 4815.75,1374.02 r45 bottom value="1 uF"
C114 "GRM033R60J475ME05D" 0201_cap#1 4784.25,1374.02 r45 bottom value="4.7 uF"
C115 "C0603X5R1E104K030BB" 0201_cap#1 4752.76,1342.52 r135 bottom value="0.1 uF"
C116 "C0603X5R1E104K030BB" 0201_cap#1 4721.26,1342.52 r315 bottom value="0.1 uF"
C117 "C0603X5R1E104K030BB" 0201_cap#1 4721.26,1311.02 r315 bottom value="0.1 uF"
C118 "GRM033R60J475ME05D" 0201_cap#1 4784.25,1248.03 r225 bottom value="4.7 uF"
C119 "GRM033R60J475ME05D" 0201_cap#1 4847.24,1232.28 r180 bottom value="4.7 uF"
C120 "GRM033R61A105ME44D" 0201_cap#1 4752.76,1248.03 r225 bottom value="1 uF"
C121 "C0603X5R1E104K030BB" 0201_cap#1 5004.72,1342.52 r45 bottom value="0.1 uF"
C122 "C1005X5R1A475K050BE" 0402L_cap#1 1249.61,723.35 r270 top value="4.7 uF"
C123 "C0603X5R1E104K030BB" 0201_cap#1 5036.22,1200.76 r180 bottom value="0.1 uF"
C124 "C1005X5R1A475K050BE" 0402L_cap#1 1249.61,1023.35 r270 top value="4.7 uF"
C125 "C0603X5R1E104K030BB" 0201_cap#1 5036.22,1295.28 r180 bottom value="0.1 uF"
C126 "0603ZD106KAT2A" 0603L_cap 266.94,1689.88 r180 bottom value="10 uF"
C127 "C0603X5R1E104K030BB" 0201_cap#1 5036.22,1389.76 r180 bottom value="0.1 uF"
C128 "04025C222JAT2A" 0402L_cap#1 264.88,1729.64 r0 bottom value="2200 pF"
C129 "C0603X5R1E104K030BB" 0201_cap#1 5036.22,1484.25 r180 bottom value="0.1 uF"
C130 "C2012X7S1A226M125AC" 0805L_cap#1 455.16,1852.2 r90 bottom value="22 uF"
C131 "C2012X7S1A226M125AC" 0805L_cap#1 515.16,1852.2 r90 bottom value="22 uF"
C132 "C0603X5R1E104K030BB" 0201_cap#1 4752.76,1405.51 r225 bottom value="0.1 uF"
C133 "C0603X5R1E104K030BB" 0201_cap#1 4784.25,1405.51 r225 bottom value="0.1 uF"
C134 "C0603X5R1E104K030BB" 0201_cap#1 4689.76,1468.5 r315 bottom value="0.1 uF"
C135 "C0603X5R1E104K030BB" 0201_cap#1 4658.27,1468.5 r315 bottom value="0.1 uF"
C136 "C0603X5R1E104K030BB" 0201_cap#1 4626.77,1468.5 r315 bottom value="0.1 uF"
C137 "C0603X5R1E104K030BB" 0201_cap#1 4595.28,1468.5 r315 bottom value="0.1 uF"
C138 "C0603X5R1E104K030BB" 0201_cap#1 4626.77,1374.02 r45 bottom value="0.1 uF"
C139 "GRM033R61A105ME44D" 0201_cap#1 4595.28,1405.51 r225 bottom value="1 uF"
C140 "GRM033R61A105ME44D" 0201_cap#1 4563.78,1374.02 r315 bottom value="1 uF"
C141 "C0603X5R1E104K030BB" 0201_cap#1 4595.28,1311.02 r135 bottom value="0.1 uF"
C142 "C0603X5R1E104K030BB" 0201_cap#1 4563.78,1295.28 r0 bottom value="0.1 uF"
C143 "C0603X5R1E104K030BB" 0201_cap#1 4626.77,1311.02 r315 bottom value="0.1 uF"
C144 "GRM033R61A105ME44D" 0201_cap#1 4658.27,1311.02 r315 bottom value="1 uF"
C145 "GRM033R60J475ME05D" 0201_cap#1 4689.76,1311.02 r315 bottom value="4.7 uF"
C146 "GRM033R60J475ME05D" 0201_cap#1 4689.76,1374.02 r45 bottom value="4.7 uF"
C147 "GRM033R61A105ME44D" 0201_cap#1 4658.27,1374.02 r45 bottom value="1 uF"
C148 "C0603X5R1E104K030BB" 0201_cap#1 4563.78,1153.54 r45 bottom value="0.1 uF"
C149 "C0603X5R1E104K030BB" 0201_cap#1 4595.28,1153.54 r45 bottom value="0.1 uF"
C150 "C0603X5R1E104K030BB" 0201_cap#1 4626.77,1153.54 r45 bottom value="0.1 uF"
C151 "C0603X5R1E104K030BB" 0201_cap#1 4658.27,1153.54 r45 bottom value="0.1 uF"
C152 "C0603X5R1E104K030BB" 0201_cap#1 4689.76,1153.54 r45 bottom value="0.1 uF"
C153 "C0603X5R1E104K030BB" 0201_cap#1 4563.78,1216.51 r315 bottom value="0.1 uF"
C154 "C0603X5R1E104K030BB" 0201_cap#1 4752.76,1279.53 r225 bottom value="0.1 uF"
C155 "C0603X5R1E104K030BB" 0201_cap#1 4595.28,1216.51 r315 bottom value="0.1 uF"
C156 "C0603X5R1E104K030BB" 0201_cap#1 4689.76,1248.03 r225 bottom value="0.1 uF"
C157 "GRM033R61A105ME44D" 0201_cap#1 4689.76,1122.05 r225 bottom value="1 uF"
C158 "C0603X5R1E104K030BB" 0201_cap#1 4689.76,1562.99 r315 bottom value="0.1 uF"
C159 "C0603X5R1E104K030BB" 0201_cap#1 4658.27,1562.99 r315 bottom value="0.1 uF"
C160 "C0603X5R1E104K030BB" 0201_cap#1 4626.77,1562.99 r315 bottom value="0.1 uF"
C161 "C0603X5R1E104K030BB" 0201_cap#1 4595.28,1562.99 r315 bottom value="0.1 uF"
C162 "C0603X5R1E104K030BB" 0201_cap#1 4563.78,1562.99 r315 bottom value="0.1 uF"
C163 "C0603X5R1E104K030BB" 0201_cap#1 4563.78,1500 r45 bottom value="0.1 uF"
C164 "GRM033R60J475ME05D" 0201_cap#1 4847.24,1484.25 r180 bottom value="4.7 uF"
C165 "GRM033R61A105ME44D" 0201_cap#1 4689.76,1610.24 r180 bottom value="1 uF"
C166 "C0603X5R1E104K030BB" 0201_cap#1 4563.78,1610.24 r0 bottom value="0.1 uF"
C167 "C2012X7S1A226M125AC" 0805L_cap#1 455.16,1743.15 r270 bottom value="22 uF"
C168 "C0603X5R1E104K030BB" 0201_cap#1 4563.78,1106.3 r0 bottom value="0.1 uF"
C169 "C0603X5R1E104K030BB" 0201_cap#1 5020.47,1562.99 r270 bottom value="0.1 uF"
C170 "C2012X7S1A226M125AC" 0805L_cap#1 546.65,1719.52 r180 bottom value="22 uF"
C171 "1210YD476KAT2A" 1210L_cap 439.97,1279.25 r180 bottom value="47 uF"
C172 "1210YD476KAT2A" 1210L_cap 439.97,1624.29 r180 bottom value="47 uF"
C173 "1210YD476KAT2A" 1210L_cap 439.97,829.76 r180 bottom value="47 uF"
C174 "1210YD476KAT2A" 1210L_cap 439.97,1174.8 r180 bottom value="47 uF"
C175 "04026D104KAT4A" 0402L_cap#2 1561.46,952.03 r90 bottom value="0.1 uF"
C176 "04026D104KAT4A" 0402L_cap#2 1755.37,923.95 r180 bottom value="0.1 uF"
C177 "04026D104KAT4A" 0402L_cap#2 1478.5,1282.81 r180 bottom value="0.1 uF"
C178 "C0603X5R1E104K030BB" 0201_cap#2 729.29,1744.85 r270 top value="0.1 uF"
C179 "C0603X5R1E104K030BB" 0201_cap#1 4570.73,944.29 r0 bottom value="0.1 uF"
C180 "C0603X5R1E104K030BB" 0201_cap#1 4721.26,1468.5 r315 bottom value="0.1 uF"
C181 "C0603X5R1E104K030BB" 0201_cap#2 2299.91,559.07 r270 bottom value="0.1 uF"
C182 "C0603X5R1E104K030BB" 0201_cap#2 1785.49,2241.68 r180 bottom value="0.1 uF"
C183 "C0603X5R1E104K030BB" 0201_cap#1 1907.71,1277.09 r270 bottom value="0.1 uF"
C184 "GMC21X5R107M6R3NT" 0805L_cap#2 880.9,1822.9 r0 bottom value="100 uF"
C185 "C0603X5R1E104K030BB" 0201_cap#1 1823.1,1150.63 r270 bottom value="0.1 uF"
C186 "C0603X5R1E104K030BB" 0201_cap#1 1852.79,1150.63 r270 bottom value="0.1 uF"
C187 "GMC21X5R107M6R3NT" 0805L_cap#2 995.96,1885.9 r180 bottom value="100 uF"
C188 "GMC21X5R107M6R3NT" 0805L_cap#2 995.96,1822.9 r180 bottom value="100 uF"
C189 "GMC21X5R107M6R3NT" 0805L_cap#2 880.9,1759.9 r0 bottom value="100 uF"
C204 "GRM155C80J106ME11D" 0402L_cap#1 622.24,1947.48 r0 bottom value="10 uF"
C205 "C1005X7S1C474K050BC" 0402L_cap#1 129.41,1807.64 r0 bottom value="0.47 uF"
C208 "C1005X5R1E105K050BC" 0402L_cap#1 818.54,1466.04 r0 bottom value="1 uF"
C209 "C1005X5R1E105K050BC" 0402L_cap#1 818.54,1443.41 r0 bottom value="1 uF"
C213 "GRT32EC70J107ME13L" 1210L_cap 782.67,1568.9 r270 bottom value="100 uF"
C214 "GRT32EC70J107ME13L" 1210L_cap 782.67,1334.65 r90 bottom value="100 uF"
C215 "GRM155C80J106ME11D" 0402L_cap#1 183.42,1275.63 r270 bottom value="10 uF"
C216 "GRT32EC70J107ME13L" 1210L_cap 662.67,1334.65 r90 bottom value="100 uF"
C217 "GRT32EC70J107ME13L" 1210L_cap 662.67,1568.9 r270 bottom value="100 uF"
C218 "C1005X6S1C225K050BC" 0402L_cap#1 228.69,1481.3 r0 bottom value="2.2 uF"
C221 "C1005X5R1E105K050BC" 0402L_cap#1 949.64,1050.11 r270 bottom value="1 uF"
C222 "C1005X5R1E105K050BC" 0402L_cap#1 919.64,1050.11 r270 bottom value="1 uF"
C223 "GRT32EC70J107ME13L" 1210L_cap 662.67,885.15 r90 bottom value="100 uF"
C224 "GRT32EC70J107ME13L" 1210L_cap 782.67,885.15 r90 bottom value="100 uF"
C225 "GRT32EC70J107ME13L" 1210L_cap 662.67,1119.41 r270 bottom value="100 uF"
C226 "GRT32EC70J107ME13L" 1210L_cap 782.67,1119.41 r270 bottom value="100 uF"
C227 "C1005X6S1C225K050BC" 0402L_cap#1 228.69,1031.81 r0 bottom value="2.2 uF"
C228 "C1005X5R1H104K050BB" 0402L_cap#1 1074.37,1716.26 r270 top value="0.1 uF"
C229 "0603ZD106KAT2A" 0603L_cap 1256.5,1727.07 r270 top value="10 uF"
C230 "C1005X5R1E105K050BC" 0402L_cap#1 1431.18,1800.55 r270 top value="1 uF"
C233 "GRM155C80J106ME11D" 0402L_cap#1 1234.29,1807.95 r180 top value="10 uF"
C235 "04026D104KAT4A" 0402L_cap#1 1074.37,1416.26 r270 top value="0.1 uF"
C236 "0603ZD106KAT2A" 0603L_cap 1256.5,1427.07 r270 top value="10 uF"
C237 "C1005X5R1E105K050BC" 0402L_cap#1 1431.18,1500.55 r270 top value="1 uF"
C240 "GRM155C80J106ME11D" 0402L_cap#1 1234.29,1507.95 r180 top value="10 uF"
C242 "04026D104KAT4A" 0402L_cap#1 1074.37,816.26 r270 top value="0.1 uF"
C243 "0603ZD106KAT2A" 0603L_cap 1256.5,827.07 r270 top value="10 uF"
C244 "C1005X5R1E105K050BC" 0402L_cap#1 1431.18,900.55 r270 top value="1 uF"
C247 "GRM155C80J106ME11D" 0402L_cap#1 1234.29,907.95 r180 top value="10 uF"
C249 "04026D104KAT4A" 0402L_cap#1 1074.37,1116.26 r270 top value="0.1 uF"
C250 "0603ZD106KAT2A" 0603L_cap 1256.5,1127.07 r270 top value="10 uF"
C251 "C1005X5R1E105K050BC" 0402L_cap#1 1431.18,1200.55 r270 top value="1 uF"
C254 "GRM155C80J106ME11D" 0402L_cap#1 1234.29,1207.95 r180 top value="10 uF"
C256 "C0603X5R1E104K030BB" 0201_cap#1 5331.04,2443.87 r90 bottom value="0.1 uF"
C258 "C0603X5R1E104K030BB" 0201_cap#1 5287.73,2229.98 r90 bottom value="0.1 uF"
C259 "C0603X5R1E104K030BB" 0201_cap#1 2841.84,2118.29 r270 bottom value="0.1 uF"
C260 "C0603X5R1E104K030BB" 0201_cap#1 2812.79,2118.29 r270 bottom value="0.1 uF"
C261 "C0603X5R1E104K030BB" 0201_cap#1 5230.7,2265.5 r180 bottom value="0.1 uF"
C262 "C0603X5R1E104K030BB" 0201_cap#1 5230.7,2290.55 r180 bottom value="0.1 uF"
C263 "C0603X5R1E104K030BB" 0201_cap#1 4333.62,1538.27 r0 bottom value="0.1 uF"
C264 "C0603X5R1E104K030BB" 0201_cap#1 4408.11,753.07 r45 bottom value="0.1 uF"
C265 "0201BB104KW160" 0201_cap#1 4189.96,380.83 r225 bottom value="0.1 uF"
D1 "LTST-C191TGKT" LED_LTST-C190-Green 5940.95,2408.52 r0 top
D2 "LTST-C191TGKT" LED_LTST-C190-Green 5727.89,2408.51 r180 top
D3 "LTST-C191TGKT" LED_LTST-C190-Green 1272.68,98.59 r0 top
D4 "SMBJ15CA" SMBJ15CA 886.96,473.35 r90 bottom
D5 "MBR130T1G" SOD-123 1471.26,267.86 r270 bottom
D6 "SDM40E20LC-7" SOT-323-DIO 6048.23,128.83 r180 bottom
F1 "SF-1206FP250-2" SF-1206F500M-2_1206 1266.46,503.35 r180 bottom
F2 "BNX002-11" FIL_BNX002-11 659.77,481.72 r90 top
FB1 "BLE18PS080SN1D" 0603L 542.72,1777.67 r0 bottom value=-
FB2 "BLE18PS080SN1D" 0603L 1552.52,1775.95 r180 top value=-
FB3 "BLE18PS080SN1D" 0603L 1552.52,1475.95 r180 top value=-
FB4 "BLE18PS080SN1D" 0603L 857.08,980.51 r0 bottom value=-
